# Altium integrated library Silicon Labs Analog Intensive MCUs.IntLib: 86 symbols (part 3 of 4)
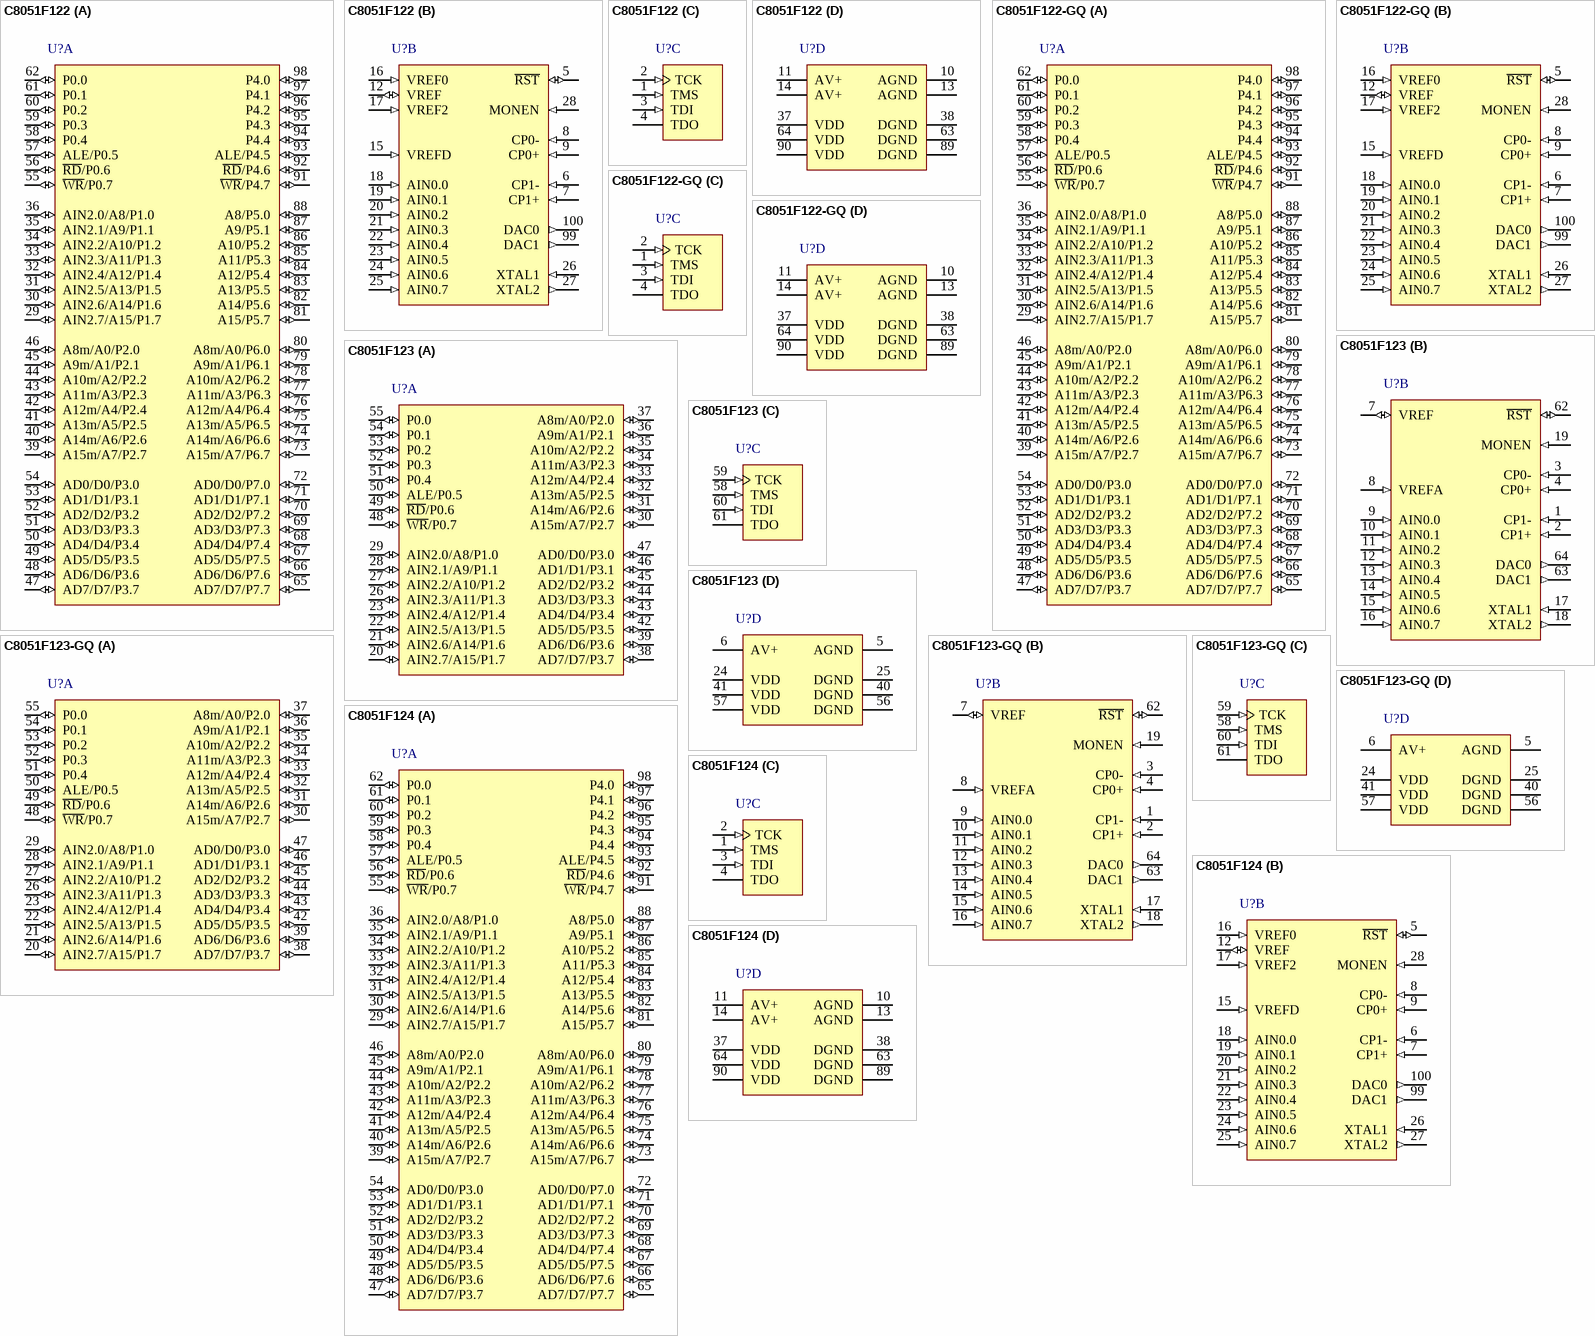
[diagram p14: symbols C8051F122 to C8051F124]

## C8051F123-GQ
designator U?
Mixed Signal 128KB ISP Flash MCU, 100 MIPS, 8448B RAM, 32 I/Os, 10-Bit & 8-Bit ADC, 12-Bit DAC, 64-Pin TQFP, Pb-Free; Manufacturer: Silicon Labs; PartNumber: C8051F123-GQ
footprint TQFP-64_N (Thin QFP, 64-Leads, Body 10x10mm, Pitch 0.5mm, IPC Medium Density)
footprint TQFP-64_L (Thin QFP, 64-Leads, Body 10x10mm, Pitch 0.5mm, IPC High Density)
footprint TQFP-64_M (Thin QFP, 64-Leads, Body 10x10mm, Pitch 0.5mm, IPC Low Density)
part A pins: 20 AIN2.7/A15/P1.7 (io), 21 AIN2.6/A14/P1.6 (io), 22 AIN2.5/A13/P1.5 (io), 23 AIN2.4/A12/P1.4 (io), 26 AIN2.3/A11/P1.3 (io), 27 AIN2.2/A10/P1.2 (io), 28 AIN2.1/A9/P1.1 (io), 29 AIN2.0/A8/P1.0 (io), 30 A15m/A7/P2.7 (io), 31 A14m/A6/P2.6 (io), 32 A13m/A5/P2.5 (io), 33 A12m/A4/P2.4 (io), 34 A11m/A3/P2.3 (io), 35 A10m/A2/P2.2 (io), 36 A9m/A1/P2.1 (io), 37 A8m/A0/P2.0 (io), 38 AD7/D7/P3.7 (io), 39 AD6/D6/P3.6 (io), 42 AD5/D5/P3.5 (io), 43 AD4/D4/P3.4 (io), 44 AD3/D3/P3.3 (io), 45 AD2/D2/P3.2 (io), 46 AD1/D1/P3.1 (io), 47 AD0/D0/P3.0 (io), 48 ~{WR}/P0.7 (io), 49 ~{RD}/P0.6 (io), 50 ALE/P0.5 (io), 51 P0.4 (io), 52 P0.3 (io), 53 P0.2 (io), 54 P0.1 (io), 55 P0.0 (io)
part B pins: 1 CP1- (in), 2 CP1+ (in), 3 CP0- (in), 4 CP0+ (in), 7 VREF (io), 8 VREFA (in), 9 AIN0.0 (in), 10 AIN0.1 (in), 11 AIN0.2 (in), 12 AIN0.3 (in), 13 AIN0.4 (in), 14 AIN0.5 (in), 15 AIN0.6 (in), 16 AIN0.7 (in), 17 XTAL1 (in), 18 XTAL2 (out), 19 MONEN (in), 62 ~{RST} (io), 63 DAC1 (out), 64 DAC0 (out)
part C pins: 58 TMS (in), 59 TCK (in), 60 TDI (in), 61 TDO (hiz)
part D pins: 5 AGND (power), 6 AV+ (power), 24 VDD (power), 25 DGND (power), 40 DGND (power), 41 VDD (power), 56 DGND (power), 57 VDD (power)

## C8051F124
designator U?
Mixed Signal 128KB ISP Flash MCU, 50 MIPS, 8448B RAM, 64 I/Os, 12-Bit & 8-Bit ADC, 12-Bit DAC, 100-Pin TQFP; Manufacturer: Silicon Labs; PartNumber: C8051F124
footprint TQFP-100_N (Thin QFP, 100-Leads, Body 14x14mm, Pitch 0.5mm, IPC Medium Density)
footprint TQFP-100_L (Thin QFP, 100-Leads, Body 14x14mm, Pitch 0.5mm, IPC High Density)
footprint TQFP-100_M (Thin QFP, 100-Leads, Body 14x14mm, Pitch 0.5mm, IPC Low Density)
part A pins: 29 AIN2.7/A15/P1.7 (io), 30 AIN2.6/A14/P1.6 (io), 31 AIN2.5/A13/P1.5 (io), 32 AIN2.4/A12/P1.4 (io), 33 AIN2.3/A11/P1.3 (io), 34 AIN2.2/A10/P1.2 (io), 35 AIN2.1/A9/P1.1 (io), 36 AIN2.0/A8/P1.0 (io), 39 A15m/A7/P2.7 (io), 40 A14m/A6/P2.6 (io), 41 A13m/A5/P2.5 (io), 42 A12m/A4/P2.4 (io), 43 A11m/A3/P2.3 (io), 44 A10m/A2/P2.2 (io), 45 A9m/A1/P2.1 (io), 46 A8m/A0/P2.0 (io), 47 AD7/D7/P3.7 (io), 48 AD6/D6/P3.6 (io), 49 AD5/D5/P3.5 (io), 50 AD4/D4/P3.4 (io), 51 AD3/D3/P3.3 (io), 52 AD2/D2/P3.2 (io), 53 AD1/D1/P3.1 (io), 54 AD0/D0/P3.0 (io), 55 ~{WR}/P0.7 (io), 56 ~{RD}/P0.6 (io), 57 ALE/P0.5 (io), 58 P0.4 (io), 59 P0.3 (io), 60 P0.2 (io), 61 P0.1 (io), 62 P0.0 (io), 65 AD7/D7/P7.7 (io), 66 AD6/D6/P7.6 (io), 67 AD5/D5/P7.5 (io), 68 AD4/D4/P7.4 (io), 69 AD3/D3/P7.3 (io), 70 AD2/D2/P7.2 (io), 71 AD1/D1/P7.1 (io), 72 AD0/D0/P7.0 (io), 73 A15m/A7/P6.7 (io), 74 A14m/A6/P6.6 (io), 75 A13m/A5/P6.5 (io), 76 A12m/A4/P6.4 (io), 77 A11m/A3/P6.3 (io), 78 A10m/A2/P6.2 (io), 79 A9m/A1/P6.1 (io), 80 A8m/A0/P6.0 (io), 81 A15/P5.7 (io), 82 A14/P5.6 (io), 83 A13/P5.5 (io), 84 A12/P5.4 (io), 85 A11/P5.3 (io), 86 A10/P5.2 (io), 87 A9/P5.1 (io), 88 A8/P5.0 (io), 91 ~{WR}/P4.7 (io), 92 ~{RD}/P4.6 (io), 93 ALE/P4.5 (io), 94 P4.4 (io), 95 P4.3 (io), 96 P4.2 (io), 97 P4.1 (io), 98 P4.0 (io)
part B pins: 5 ~{RST} (io), 6 CP1- (in), 7 CP1+ (in), 8 CP0- (in), 9 CP0+ (in), 12 VREF (io), 15 VREFD (in), 16 VREF0 (in), 17 VREF2 (in), 18 AIN0.0 (in), 19 AIN0.1 (in), 20 AIN0.2 (in), 21 AIN0.3 (in), 22 AIN0.4 (in), 23 AIN0.5 (in), 24 AIN0.6 (in), 25 AIN0.7 (in), 26 XTAL1 (in), 27 XTAL2 (out), 28 MONEN (in), 99 DAC1 (out), 100 DAC0 (out)
part C pins: 1 TMS (in), 2 TCK (in), 3 TDI (in), 4 TDO (hiz)
part D pins: 10 AGND (power), 11 AV+ (power), 13 AGND (power), 14 AV+ (power), 37 VDD (power), 38 DGND (power), 63 DGND (power), 64 VDD (power), 89 DGND (power), 90 VDD (power)

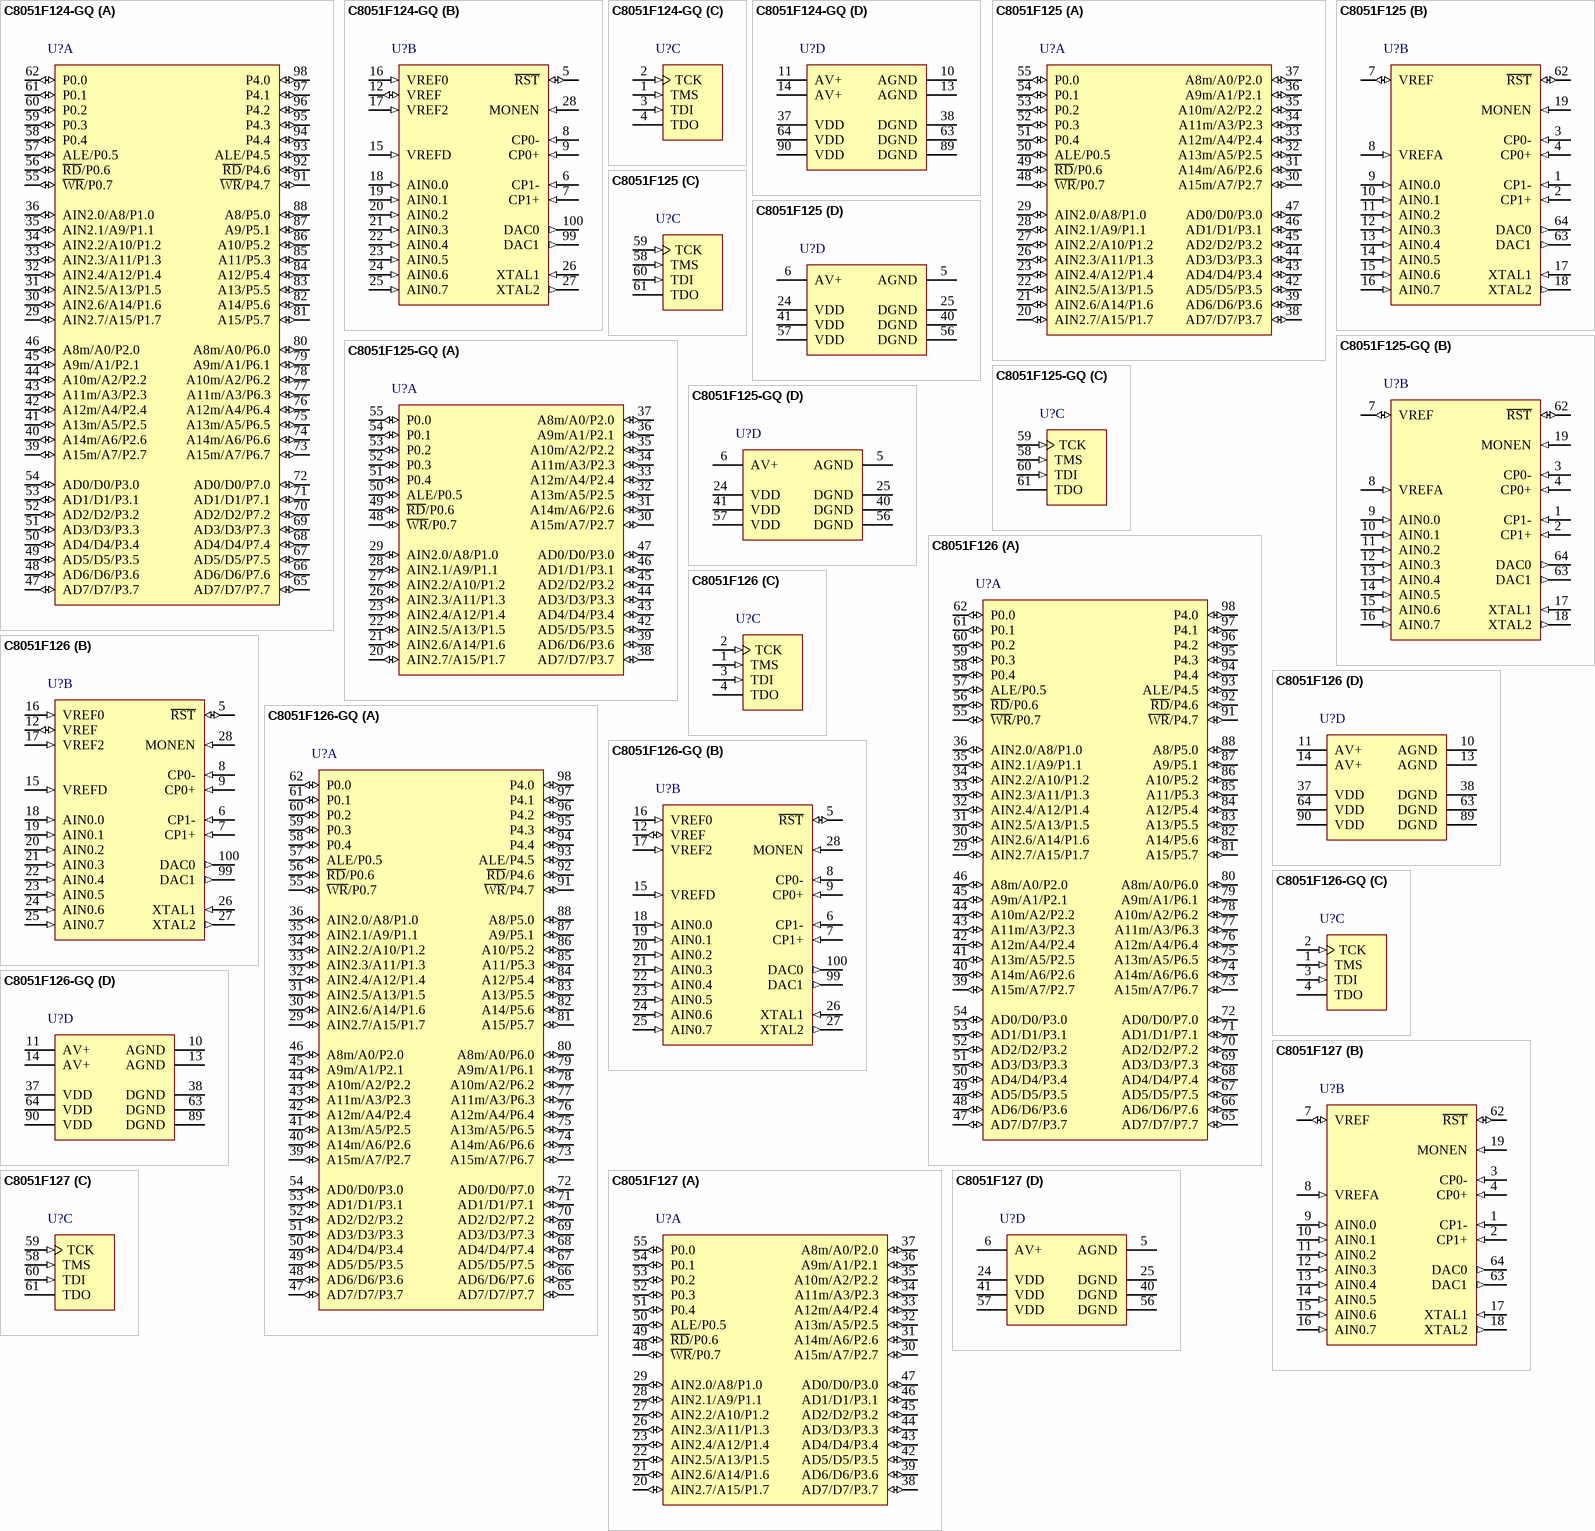
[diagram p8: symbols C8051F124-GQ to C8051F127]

## C8051F124-GQ
designator U?
Mixed Signal 128KB ISP Flash MCU, 50 MIPS, 8448B RAM, 64 I/Os, 12-Bit & 8-Bit ADC, 12-Bit DAC, 100-Pin TQFP, Pb-Free; Manufacturer: Silicon Labs; PartNumber: C8051F124-GQ
footprint TQFP-100_N (Thin QFP, 100-Leads, Body 14x14mm, Pitch 0.5mm, IPC Medium Density)
footprint TQFP-100_L (Thin QFP, 100-Leads, Body 14x14mm, Pitch 0.5mm, IPC High Density)
footprint TQFP-100_M (Thin QFP, 100-Leads, Body 14x14mm, Pitch 0.5mm, IPC Low Density)
part A pins: 29 AIN2.7/A15/P1.7 (io), 30 AIN2.6/A14/P1.6 (io), 31 AIN2.5/A13/P1.5 (io), 32 AIN2.4/A12/P1.4 (io), 33 AIN2.3/A11/P1.3 (io), 34 AIN2.2/A10/P1.2 (io), 35 AIN2.1/A9/P1.1 (io), 36 AIN2.0/A8/P1.0 (io), 39 A15m/A7/P2.7 (io), 40 A14m/A6/P2.6 (io), 41 A13m/A5/P2.5 (io), 42 A12m/A4/P2.4 (io), 43 A11m/A3/P2.3 (io), 44 A10m/A2/P2.2 (io), 45 A9m/A1/P2.1 (io), 46 A8m/A0/P2.0 (io), 47 AD7/D7/P3.7 (io), 48 AD6/D6/P3.6 (io), 49 AD5/D5/P3.5 (io), 50 AD4/D4/P3.4 (io), 51 AD3/D3/P3.3 (io), 52 AD2/D2/P3.2 (io), 53 AD1/D1/P3.1 (io), 54 AD0/D0/P3.0 (io), 55 ~{WR}/P0.7 (io), 56 ~{RD}/P0.6 (io), 57 ALE/P0.5 (io), 58 P0.4 (io), 59 P0.3 (io), 60 P0.2 (io), 61 P0.1 (io), 62 P0.0 (io), 65 AD7/D7/P7.7 (io), 66 AD6/D6/P7.6 (io), 67 AD5/D5/P7.5 (io), 68 AD4/D4/P7.4 (io), 69 AD3/D3/P7.3 (io), 70 AD2/D2/P7.2 (io), 71 AD1/D1/P7.1 (io), 72 AD0/D0/P7.0 (io), 73 A15m/A7/P6.7 (io), 74 A14m/A6/P6.6 (io), 75 A13m/A5/P6.5 (io), 76 A12m/A4/P6.4 (io), 77 A11m/A3/P6.3 (io), 78 A10m/A2/P6.2 (io), 79 A9m/A1/P6.1 (io), 80 A8m/A0/P6.0 (io), 81 A15/P5.7 (io), 82 A14/P5.6 (io), 83 A13/P5.5 (io), 84 A12/P5.4 (io), 85 A11/P5.3 (io), 86 A10/P5.2 (io), 87 A9/P5.1 (io), 88 A8/P5.0 (io), 91 ~{WR}/P4.7 (io), 92 ~{RD}/P4.6 (io), 93 ALE/P4.5 (io), 94 P4.4 (io), 95 P4.3 (io), 96 P4.2 (io), 97 P4.1 (io), 98 P4.0 (io)
part B pins: 5 ~{RST} (io), 6 CP1- (in), 7 CP1+ (in), 8 CP0- (in), 9 CP0+ (in), 12 VREF (io), 15 VREFD (in), 16 VREF0 (in), 17 VREF2 (in), 18 AIN0.0 (in), 19 AIN0.1 (in), 20 AIN0.2 (in), 21 AIN0.3 (in), 22 AIN0.4 (in), 23 AIN0.5 (in), 24 AIN0.6 (in), 25 AIN0.7 (in), 26 XTAL1 (in), 27 XTAL2 (out), 28 MONEN (in), 99 DAC1 (out), 100 DAC0 (out)
part C pins: 1 TMS (in), 2 TCK (in), 3 TDI (in), 4 TDO (hiz)
part D pins: 10 AGND (power), 11 AV+ (power), 13 AGND (power), 14 AV+ (power), 37 VDD (power), 38 DGND (power), 63 DGND (power), 64 VDD (power), 89 DGND (power), 90 VDD (power)

## C8051F125
designator U?
Mixed Signal 128KB ISP Flash MCU, 50 MIPS, 8448B RAM, 32 I/Os, 12-Bit & 8-Bit ADC, 12-Bit DAC, 64-Pin TQFP; Manufacturer: Silicon Labs; PartNumber: C8051F125
footprint TQFP-64_N (Thin QFP, 64-Leads, Body 10x10mm, Pitch 0.5mm, IPC Medium Density)
footprint TQFP-64_L (Thin QFP, 64-Leads, Body 10x10mm, Pitch 0.5mm, IPC High Density)
footprint TQFP-64_M (Thin QFP, 64-Leads, Body 10x10mm, Pitch 0.5mm, IPC Low Density)
part A pins: 20 AIN2.7/A15/P1.7 (io), 21 AIN2.6/A14/P1.6 (io), 22 AIN2.5/A13/P1.5 (io), 23 AIN2.4/A12/P1.4 (io), 26 AIN2.3/A11/P1.3 (io), 27 AIN2.2/A10/P1.2 (io), 28 AIN2.1/A9/P1.1 (io), 29 AIN2.0/A8/P1.0 (io), 30 A15m/A7/P2.7 (io), 31 A14m/A6/P2.6 (io), 32 A13m/A5/P2.5 (io), 33 A12m/A4/P2.4 (io), 34 A11m/A3/P2.3 (io), 35 A10m/A2/P2.2 (io), 36 A9m/A1/P2.1 (io), 37 A8m/A0/P2.0 (io), 38 AD7/D7/P3.7 (io), 39 AD6/D6/P3.6 (io), 42 AD5/D5/P3.5 (io), 43 AD4/D4/P3.4 (io), 44 AD3/D3/P3.3 (io), 45 AD2/D2/P3.2 (io), 46 AD1/D1/P3.1 (io), 47 AD0/D0/P3.0 (io), 48 ~{WR}/P0.7 (io), 49 ~{RD}/P0.6 (io), 50 ALE/P0.5 (io), 51 P0.4 (io), 52 P0.3 (io), 53 P0.2 (io), 54 P0.1 (io), 55 P0.0 (io)
part B pins: 1 CP1- (in), 2 CP1+ (in), 3 CP0- (in), 4 CP0+ (in), 7 VREF (io), 8 VREFA (in), 9 AIN0.0 (in), 10 AIN0.1 (in), 11 AIN0.2 (in), 12 AIN0.3 (in), 13 AIN0.4 (in), 14 AIN0.5 (in), 15 AIN0.6 (in), 16 AIN0.7 (in), 17 XTAL1 (in), 18 XTAL2 (out), 19 MONEN (in), 62 ~{RST} (io), 63 DAC1 (out), 64 DAC0 (out)
part C pins: 58 TMS (in), 59 TCK (in), 60 TDI (in), 61 TDO (hiz)
part D pins: 5 AGND (power), 6 AV+ (power), 24 VDD (power), 25 DGND (power), 40 DGND (power), 41 VDD (power), 56 DGND (power), 57 VDD (power)

## C8051F125-GQ
designator U?
Mixed Signal 128KB ISP Flash MCU, 50 MIPS, 8448B RAM, 32 I/Os, 12-Bit & 8-Bit ADC, 12-Bit DAC, 64-Pin TQFP, Pb-Free; Manufacturer: Silicon Labs; PartNumber: C8051F125-GQ
footprint TQFP-64_N (Thin QFP, 64-Leads, Body 10x10mm, Pitch 0.5mm, IPC Medium Density)
footprint TQFP-64_L (Thin QFP, 64-Leads, Body 10x10mm, Pitch 0.5mm, IPC High Density)
footprint TQFP-64_M (Thin QFP, 64-Leads, Body 10x10mm, Pitch 0.5mm, IPC Low Density)
part A pins: 20 AIN2.7/A15/P1.7 (io), 21 AIN2.6/A14/P1.6 (io), 22 AIN2.5/A13/P1.5 (io), 23 AIN2.4/A12/P1.4 (io), 26 AIN2.3/A11/P1.3 (io), 27 AIN2.2/A10/P1.2 (io), 28 AIN2.1/A9/P1.1 (io), 29 AIN2.0/A8/P1.0 (io), 30 A15m/A7/P2.7 (io), 31 A14m/A6/P2.6 (io), 32 A13m/A5/P2.5 (io), 33 A12m/A4/P2.4 (io), 34 A11m/A3/P2.3 (io), 35 A10m/A2/P2.2 (io), 36 A9m/A1/P2.1 (io), 37 A8m/A0/P2.0 (io), 38 AD7/D7/P3.7 (io), 39 AD6/D6/P3.6 (io), 42 AD5/D5/P3.5 (io), 43 AD4/D4/P3.4 (io), 44 AD3/D3/P3.3 (io), 45 AD2/D2/P3.2 (io), 46 AD1/D1/P3.1 (io), 47 AD0/D0/P3.0 (io), 48 ~{WR}/P0.7 (io), 49 ~{RD}/P0.6 (io), 50 ALE/P0.5 (io), 51 P0.4 (io), 52 P0.3 (io), 53 P0.2 (io), 54 P0.1 (io), 55 P0.0 (io)
part B pins: 1 CP1- (in), 2 CP1+ (in), 3 CP0- (in), 4 CP0+ (in), 7 VREF (io), 8 VREFA (in), 9 AIN0.0 (in), 10 AIN0.1 (in), 11 AIN0.2 (in), 12 AIN0.3 (in), 13 AIN0.4 (in), 14 AIN0.5 (in), 15 AIN0.6 (in), 16 AIN0.7 (in), 17 XTAL1 (in), 18 XTAL2 (out), 19 MONEN (in), 62 ~{RST} (io), 63 DAC1 (out), 64 DAC0 (out)
part C pins: 58 TMS (in), 59 TCK (in), 60 TDI (in), 61 TDO (hiz)
part D pins: 5 AGND (power), 6 AV+ (power), 24 VDD (power), 25 DGND (power), 40 DGND (power), 41 VDD (power), 56 DGND (power), 57 VDD (power)

## C8051F126
designator U?
Mixed Signal 128KB ISP Flash MCU, 50 MIPS, 8448B RAM, 64 I/Os, 10-Bit & 8-Bit ADC, 12-Bit DAC, 100-Pin TQFP; Manufacturer: Silicon Labs; PartNumber: C8051F126
footprint TQFP-100_N (Thin QFP, 100-Leads, Body 14x14mm, Pitch 0.5mm, IPC Medium Density)
footprint TQFP-100_L (Thin QFP, 100-Leads, Body 14x14mm, Pitch 0.5mm, IPC High Density)
footprint TQFP-100_M (Thin QFP, 100-Leads, Body 14x14mm, Pitch 0.5mm, IPC Low Density)
part A pins: 29 AIN2.7/A15/P1.7 (io), 30 AIN2.6/A14/P1.6 (io), 31 AIN2.5/A13/P1.5 (io), 32 AIN2.4/A12/P1.4 (io), 33 AIN2.3/A11/P1.3 (io), 34 AIN2.2/A10/P1.2 (io), 35 AIN2.1/A9/P1.1 (io), 36 AIN2.0/A8/P1.0 (io), 39 A15m/A7/P2.7 (io), 40 A14m/A6/P2.6 (io), 41 A13m/A5/P2.5 (io), 42 A12m/A4/P2.4 (io), 43 A11m/A3/P2.3 (io), 44 A10m/A2/P2.2 (io), 45 A9m/A1/P2.1 (io), 46 A8m/A0/P2.0 (io), 47 AD7/D7/P3.7 (io), 48 AD6/D6/P3.6 (io), 49 AD5/D5/P3.5 (io), 50 AD4/D4/P3.4 (io), 51 AD3/D3/P3.3 (io), 52 AD2/D2/P3.2 (io), 53 AD1/D1/P3.1 (io), 54 AD0/D0/P3.0 (io), 55 ~{WR}/P0.7 (io), 56 ~{RD}/P0.6 (io), 57 ALE/P0.5 (io), 58 P0.4 (io), 59 P0.3 (io), 60 P0.2 (io), 61 P0.1 (io), 62 P0.0 (io), 65 AD7/D7/P7.7 (io), 66 AD6/D6/P7.6 (io), 67 AD5/D5/P7.5 (io), 68 AD4/D4/P7.4 (io), 69 AD3/D3/P7.3 (io), 70 AD2/D2/P7.2 (io), 71 AD1/D1/P7.1 (io), 72 AD0/D0/P7.0 (io), 73 A15m/A7/P6.7 (io), 74 A14m/A6/P6.6 (io), 75 A13m/A5/P6.5 (io), 76 A12m/A4/P6.4 (io), 77 A11m/A3/P6.3 (io), 78 A10m/A2/P6.2 (io), 79 A9m/A1/P6.1 (io), 80 A8m/A0/P6.0 (io), 81 A15/P5.7 (io), 82 A14/P5.6 (io), 83 A13/P5.5 (io), 84 A12/P5.4 (io), 85 A11/P5.3 (io), 86 A10/P5.2 (io), 87 A9/P5.1 (io), 88 A8/P5.0 (io), 91 ~{WR}/P4.7 (io), 92 ~{RD}/P4.6 (io), 93 ALE/P4.5 (io), 94 P4.4 (io), 95 P4.3 (io), 96 P4.2 (io), 97 P4.1 (io), 98 P4.0 (io)
part B pins: 5 ~{RST} (io), 6 CP1- (in), 7 CP1+ (in), 8 CP0- (in), 9 CP0+ (in), 12 VREF (io), 15 VREFD (in), 16 VREF0 (in), 17 VREF2 (in), 18 AIN0.0 (in), 19 AIN0.1 (in), 20 AIN0.2 (in), 21 AIN0.3 (in), 22 AIN0.4 (in), 23 AIN0.5 (in), 24 AIN0.6 (in), 25 AIN0.7 (in), 26 XTAL1 (in), 27 XTAL2 (out), 28 MONEN (in), 99 DAC1 (out), 100 DAC0 (out)
part C pins: 1 TMS (in), 2 TCK (in), 3 TDI (in), 4 TDO (hiz)
part D pins: 10 AGND (power), 11 AV+ (power), 13 AGND (power), 14 AV+ (power), 37 VDD (power), 38 DGND (power), 63 DGND (power), 64 VDD (power), 89 DGND (power), 90 VDD (power)

## C8051F126-GQ
designator U?
Mixed Signal 128KB ISP Flash MCU, 50 MIPS, 8448B RAM, 64 I/Os, 10-Bit & 8-Bit ADC, 12-Bit DAC, 100-Pin TQFP, Pb-Free; Manufacturer: Silicon Labs; PartNumber: C8051F126-GQ
footprint TQFP-100_N (Thin QFP, 100-Leads, Body 14x14mm, Pitch 0.5mm, IPC Medium Density)
footprint TQFP-100_L (Thin QFP, 100-Leads, Body 14x14mm, Pitch 0.5mm, IPC High Density)
footprint TQFP-100_M (Thin QFP, 100-Leads, Body 14x14mm, Pitch 0.5mm, IPC Low Density)
part A pins: 29 AIN2.7/A15/P1.7 (io), 30 AIN2.6/A14/P1.6 (io), 31 AIN2.5/A13/P1.5 (io), 32 AIN2.4/A12/P1.4 (io), 33 AIN2.3/A11/P1.3 (io), 34 AIN2.2/A10/P1.2 (io), 35 AIN2.1/A9/P1.1 (io), 36 AIN2.0/A8/P1.0 (io), 39 A15m/A7/P2.7 (io), 40 A14m/A6/P2.6 (io), 41 A13m/A5/P2.5 (io), 42 A12m/A4/P2.4 (io), 43 A11m/A3/P2.3 (io), 44 A10m/A2/P2.2 (io), 45 A9m/A1/P2.1 (io), 46 A8m/A0/P2.0 (io), 47 AD7/D7/P3.7 (io), 48 AD6/D6/P3.6 (io), 49 AD5/D5/P3.5 (io), 50 AD4/D4/P3.4 (io), 51 AD3/D3/P3.3 (io), 52 AD2/D2/P3.2 (io), 53 AD1/D1/P3.1 (io), 54 AD0/D0/P3.0 (io), 55 ~{WR}/P0.7 (io), 56 ~{RD}/P0.6 (io), 57 ALE/P0.5 (io), 58 P0.4 (io), 59 P0.3 (io), 60 P0.2 (io), 61 P0.1 (io), 62 P0.0 (io), 65 AD7/D7/P7.7 (io), 66 AD6/D6/P7.6 (io), 67 AD5/D5/P7.5 (io), 68 AD4/D4/P7.4 (io), 69 AD3/D3/P7.3 (io), 70 AD2/D2/P7.2 (io), 71 AD1/D1/P7.1 (io), 72 AD0/D0/P7.0 (io), 73 A15m/A7/P6.7 (io), 74 A14m/A6/P6.6 (io), 75 A13m/A5/P6.5 (io), 76 A12m/A4/P6.4 (io), 77 A11m/A3/P6.3 (io), 78 A10m/A2/P6.2 (io), 79 A9m/A1/P6.1 (io), 80 A8m/A0/P6.0 (io), 81 A15/P5.7 (io), 82 A14/P5.6 (io), 83 A13/P5.5 (io), 84 A12/P5.4 (io), 85 A11/P5.3 (io), 86 A10/P5.2 (io), 87 A9/P5.1 (io), 88 A8/P5.0 (io), 91 ~{WR}/P4.7 (io), 92 ~{RD}/P4.6 (io), 93 ALE/P4.5 (io), 94 P4.4 (io), 95 P4.3 (io), 96 P4.2 (io), 97 P4.1 (io), 98 P4.0 (io)
part B pins: 5 ~{RST} (io), 6 CP1- (in), 7 CP1+ (in), 8 CP0- (in), 9 CP0+ (in), 12 VREF (io), 15 VREFD (in), 16 VREF0 (in), 17 VREF2 (in), 18 AIN0.0 (in), 19 AIN0.1 (in), 20 AIN0.2 (in), 21 AIN0.3 (in), 22 AIN0.4 (in), 23 AIN0.5 (in), 24 AIN0.6 (in), 25 AIN0.7 (in), 26 XTAL1 (in), 27 XTAL2 (out), 28 MONEN (in), 99 DAC1 (out), 100 DAC0 (out)
part C pins: 1 TMS (in), 2 TCK (in), 3 TDI (in), 4 TDO (hiz)
part D pins: 10 AGND (power), 11 AV+ (power), 13 AGND (power), 14 AV+ (power), 37 VDD (power), 38 DGND (power), 63 DGND (power), 64 VDD (power), 89 DGND (power), 90 VDD (power)

## C8051F127
designator U?
Mixed Signal 128KB ISP Flash MCU, 50 MIPS, 8448B RAM, 32 I/Os, 10-Bit & 8-Bit ADC, 12-Bit DAC, 64-Pin TQFP; Manufacturer: Silicon Labs; PartNumber: C8051F127
footprint TQFP-64_N (Thin QFP, 64-Leads, Body 10x10mm, Pitch 0.5mm, IPC Medium Density)
footprint TQFP-64_L (Thin QFP, 64-Leads, Body 10x10mm, Pitch 0.5mm, IPC High Density)
footprint TQFP-64_M (Thin QFP, 64-Leads, Body 10x10mm, Pitch 0.5mm, IPC Low Density)
part A pins: 20 AIN2.7/A15/P1.7 (io), 21 AIN2.6/A14/P1.6 (io), 22 AIN2.5/A13/P1.5 (io), 23 AIN2.4/A12/P1.4 (io), 26 AIN2.3/A11/P1.3 (io), 27 AIN2.2/A10/P1.2 (io), 28 AIN2.1/A9/P1.1 (io), 29 AIN2.0/A8/P1.0 (io), 30 A15m/A7/P2.7 (io), 31 A14m/A6/P2.6 (io), 32 A13m/A5/P2.5 (io), 33 A12m/A4/P2.4 (io), 34 A11m/A3/P2.3 (io), 35 A10m/A2/P2.2 (io), 36 A9m/A1/P2.1 (io), 37 A8m/A0/P2.0 (io), 38 AD7/D7/P3.7 (io), 39 AD6/D6/P3.6 (io), 42 AD5/D5/P3.5 (io), 43 AD4/D4/P3.4 (io), 44 AD3/D3/P3.3 (io), 45 AD2/D2/P3.2 (io), 46 AD1/D1/P3.1 (io), 47 AD0/D0/P3.0 (io), 48 ~{WR}/P0.7 (io), 49 ~{RD}/P0.6 (io), 50 ALE/P0.5 (io), 51 P0.4 (io), 52 P0.3 (io), 53 P0.2 (io), 54 P0.1 (io), 55 P0.0 (io)
part B pins: 1 CP1- (in), 2 CP1+ (in), 3 CP0- (in), 4 CP0+ (in), 7 VREF (io), 8 VREFA (in), 9 AIN0.0 (in), 10 AIN0.1 (in), 11 AIN0.2 (in), 12 AIN0.3 (in), 13 AIN0.4 (in), 14 AIN0.5 (in), 15 AIN0.6 (in), 16 AIN0.7 (in), 17 XTAL1 (in), 18 XTAL2 (out), 19 MONEN (in), 62 ~{RST} (io), 63 DAC1 (out), 64 DAC0 (out)
part C pins: 58 TMS (in), 59 TCK (in), 60 TDI (in), 61 TDO (hiz)
part D pins: 5 AGND (power), 6 AV+ (power), 24 VDD (power), 25 DGND (power), 40 DGND (power), 41 VDD (power), 56 DGND (power), 57 VDD (power)

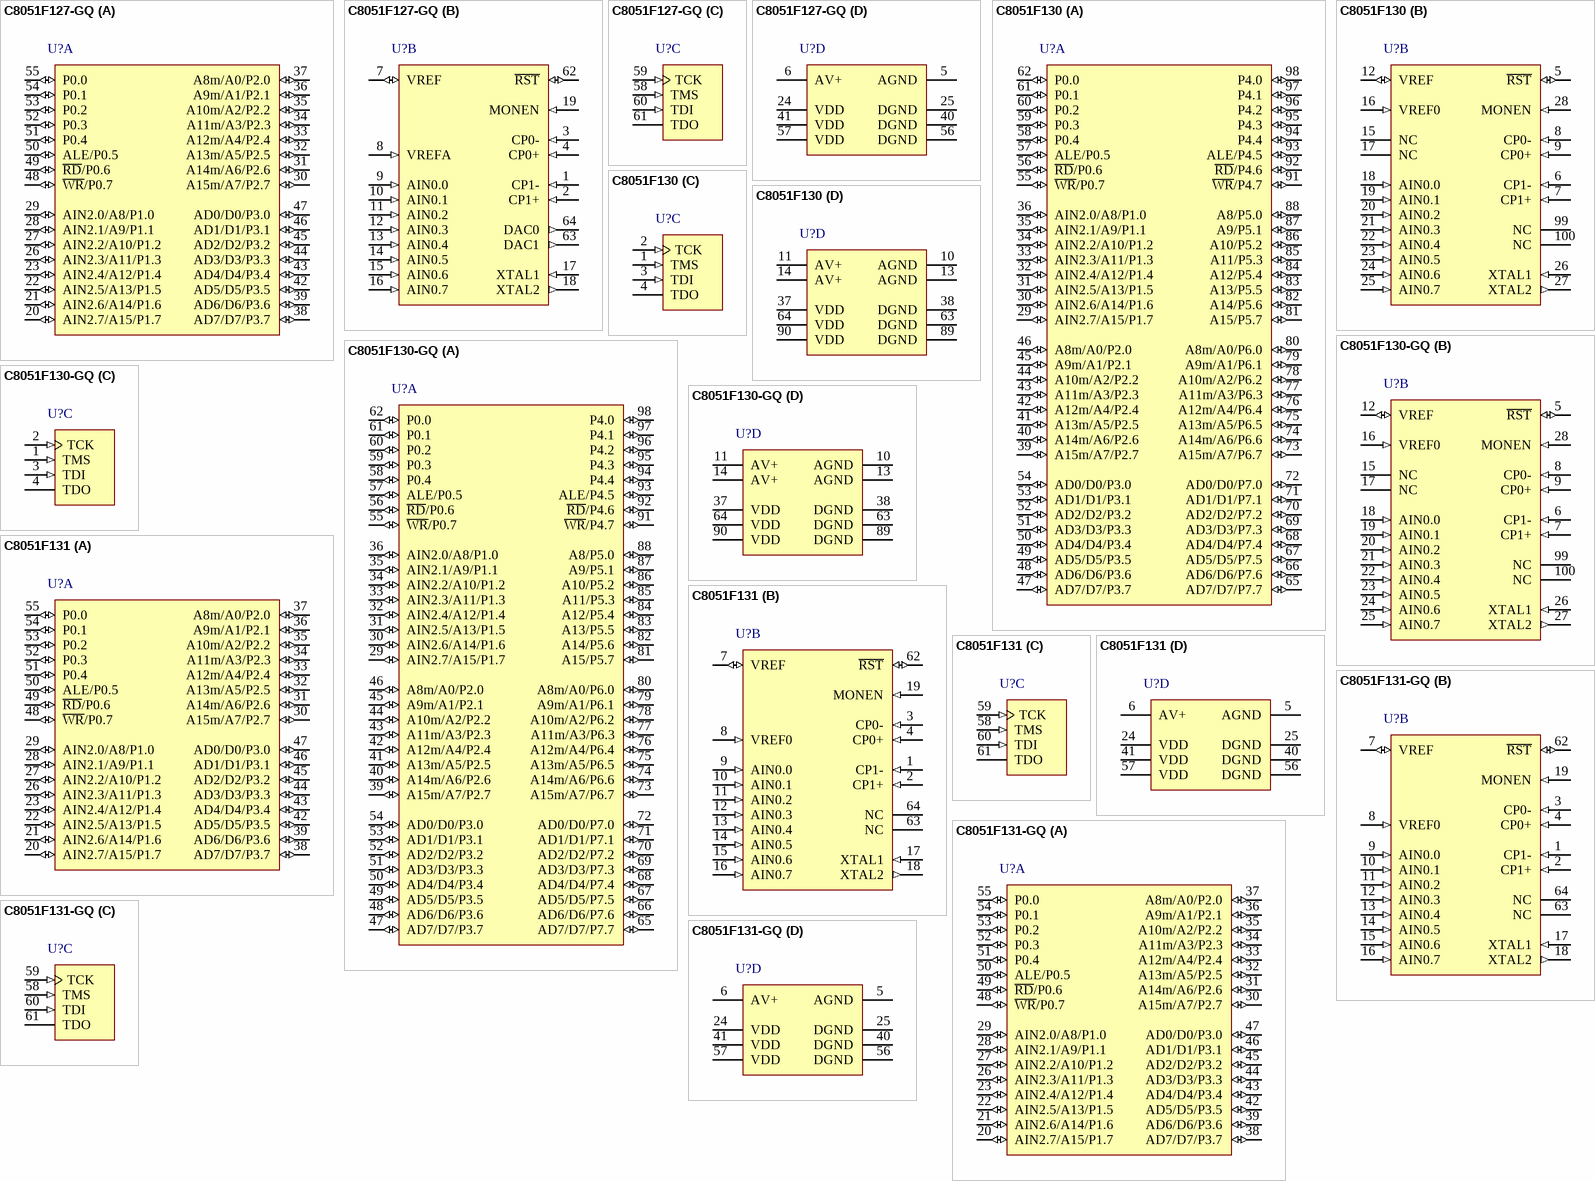
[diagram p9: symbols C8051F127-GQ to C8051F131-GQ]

## C8051F127-GQ
designator U?
Mixed Signal 128KB ISP Flash MCU, 50 MIPS, 8448B RAM, 32 I/Os, 10-Bit & 8-Bit ADC, 12-Bit DAC, 64-Pin TQFP, Pb-Free; Manufacturer: Silicon Labs; PartNumber: C8051F127-GQ
footprint TQFP-64_N (Thin QFP, 64-Leads, Body 10x10mm, Pitch 0.5mm, IPC Medium Density)
footprint TQFP-64_L (Thin QFP, 64-Leads, Body 10x10mm, Pitch 0.5mm, IPC High Density)
footprint TQFP-64_M (Thin QFP, 64-Leads, Body 10x10mm, Pitch 0.5mm, IPC Low Density)
part A pins: 20 AIN2.7/A15/P1.7 (io), 21 AIN2.6/A14/P1.6 (io), 22 AIN2.5/A13/P1.5 (io), 23 AIN2.4/A12/P1.4 (io), 26 AIN2.3/A11/P1.3 (io), 27 AIN2.2/A10/P1.2 (io), 28 AIN2.1/A9/P1.1 (io), 29 AIN2.0/A8/P1.0 (io), 30 A15m/A7/P2.7 (io), 31 A14m/A6/P2.6 (io), 32 A13m/A5/P2.5 (io), 33 A12m/A4/P2.4 (io), 34 A11m/A3/P2.3 (io), 35 A10m/A2/P2.2 (io), 36 A9m/A1/P2.1 (io), 37 A8m/A0/P2.0 (io), 38 AD7/D7/P3.7 (io), 39 AD6/D6/P3.6 (io), 42 AD5/D5/P3.5 (io), 43 AD4/D4/P3.4 (io), 44 AD3/D3/P3.3 (io), 45 AD2/D2/P3.2 (io), 46 AD1/D1/P3.1 (io), 47 AD0/D0/P3.0 (io), 48 ~{WR}/P0.7 (io), 49 ~{RD}/P0.6 (io), 50 ALE/P0.5 (io), 51 P0.4 (io), 52 P0.3 (io), 53 P0.2 (io), 54 P0.1 (io), 55 P0.0 (io)
part B pins: 1 CP1- (in), 2 CP1+ (in), 3 CP0- (in), 4 CP0+ (in), 7 VREF (io), 8 VREFA (in), 9 AIN0.0 (in), 10 AIN0.1 (in), 11 AIN0.2 (in), 12 AIN0.3 (in), 13 AIN0.4 (in), 14 AIN0.5 (in), 15 AIN0.6 (in), 16 AIN0.7 (in), 17 XTAL1 (in), 18 XTAL2 (out), 19 MONEN (in), 62 ~{RST} (io), 63 DAC1 (out), 64 DAC0 (out)
part C pins: 58 TMS (in), 59 TCK (in), 60 TDI (in), 61 TDO (hiz)
part D pins: 5 AGND (power), 6 AV+ (power), 24 VDD (power), 25 DGND (power), 40 DGND (power), 41 VDD (power), 56 DGND (power), 57 VDD (power)

## C8051F130
designator U?
Mixed Signal 128KB ISP Flash MCU, 100 MIPS, 8448B RAM, 64 I/Os, 10-Bit ADC, 100-Pin TQFP; Manufacturer: Silicon Labs; PartNumber: C8051F130
footprint TQFP-100_N (Thin QFP, 100-Leads, Body 14x14mm, Pitch 0.5mm, IPC Medium Density)
footprint TQFP-100_L (Thin QFP, 100-Leads, Body 14x14mm, Pitch 0.5mm, IPC High Density)
footprint TQFP-100_M (Thin QFP, 100-Leads, Body 14x14mm, Pitch 0.5mm, IPC Low Density)
part A pins: 29 AIN2.7/A15/P1.7 (io), 30 AIN2.6/A14/P1.6 (io), 31 AIN2.5/A13/P1.5 (io), 32 AIN2.4/A12/P1.4 (io), 33 AIN2.3/A11/P1.3 (io), 34 AIN2.2/A10/P1.2 (io), 35 AIN2.1/A9/P1.1 (io), 36 AIN2.0/A8/P1.0 (io), 39 A15m/A7/P2.7 (io), 40 A14m/A6/P2.6 (io), 41 A13m/A5/P2.5 (io), 42 A12m/A4/P2.4 (io), 43 A11m/A3/P2.3 (io), 44 A10m/A2/P2.2 (io), 45 A9m/A1/P2.1 (io), 46 A8m/A0/P2.0 (io), 47 AD7/D7/P3.7 (io), 48 AD6/D6/P3.6 (io), 49 AD5/D5/P3.5 (io), 50 AD4/D4/P3.4 (io), 51 AD3/D3/P3.3 (io), 52 AD2/D2/P3.2 (io), 53 AD1/D1/P3.1 (io), 54 AD0/D0/P3.0 (io), 55 ~{WR}/P0.7 (io), 56 ~{RD}/P0.6 (io), 57 ALE/P0.5 (io), 58 P0.4 (io), 59 P0.3 (io), 60 P0.2 (io), 61 P0.1 (io), 62 P0.0 (io), 65 AD7/D7/P7.7 (io), 66 AD6/D6/P7.6 (io), 67 AD5/D5/P7.5 (io), 68 AD4/D4/P7.4 (io), 69 AD3/D3/P7.3 (io), 70 AD2/D2/P7.2 (io), 71 AD1/D1/P7.1 (io), 72 AD0/D0/P7.0 (io), 73 A15m/A7/P6.7 (io), 74 A14m/A6/P6.6 (io), 75 A13m/A5/P6.5 (io), 76 A12m/A4/P6.4 (io), 77 A11m/A3/P6.3 (io), 78 A10m/A2/P6.2 (io), 79 A9m/A1/P6.1 (io), 80 A8m/A0/P6.0 (io), 81 A15/P5.7 (io), 82 A14/P5.6 (io), 83 A13/P5.5 (io), 84 A12/P5.4 (io), 85 A11/P5.3 (io), 86 A10/P5.2 (io), 87 A9/P5.1 (io), 88 A8/P5.0 (io), 91 ~{WR}/P4.7 (io), 92 ~{RD}/P4.6 (io), 93 ALE/P4.5 (io), 94 P4.4 (io), 95 P4.3 (io), 96 P4.2 (io), 97 P4.1 (io), 98 P4.0 (io)
part B pins: 5 ~{RST} (io), 6 CP1- (in), 7 CP1+ (in), 8 CP0- (in), 9 CP0+ (in), 12 VREF (io), 15 NC, 16 VREF0 (in), 17 NC, 18 AIN0.0 (in), 19 AIN0.1 (in), 20 AIN0.2 (in), 21 AIN0.3 (in), 22 AIN0.4 (in), 23 AIN0.5 (in), 24 AIN0.6 (in), 25 AIN0.7 (in), 26 XTAL1 (in), 27 XTAL2 (out), 28 MONEN (in), 99 NC, 100 NC
part C pins: 1 TMS (in), 2 TCK (in), 3 TDI (in), 4 TDO (hiz)
part D pins: 10 AGND (power), 11 AV+ (power), 13 AGND (power), 14 AV+ (power), 37 VDD (power), 38 DGND (power), 63 DGND (power), 64 VDD (power), 89 DGND (power), 90 VDD (power)

## C8051F130-GQ
designator U?
Mixed Signal 128KB ISP Flash MCU, 100 MIPS, 8448B RAM, 64 I/Os, 10-Bit ADC, 100-Pin TQFP, Pb-Free; Manufacturer: Silicon Labs; PartNumber: C8051F130-GQ
footprint TQFP-100_N (Thin QFP, 100-Leads, Body 14x14mm, Pitch 0.5mm, IPC Medium Density)
footprint TQFP-100_L (Thin QFP, 100-Leads, Body 14x14mm, Pitch 0.5mm, IPC High Density)
footprint TQFP-100_M (Thin QFP, 100-Leads, Body 14x14mm, Pitch 0.5mm, IPC Low Density)
part A pins: 29 AIN2.7/A15/P1.7 (io), 30 AIN2.6/A14/P1.6 (io), 31 AIN2.5/A13/P1.5 (io), 32 AIN2.4/A12/P1.4 (io), 33 AIN2.3/A11/P1.3 (io), 34 AIN2.2/A10/P1.2 (io), 35 AIN2.1/A9/P1.1 (io), 36 AIN2.0/A8/P1.0 (io), 39 A15m/A7/P2.7 (io), 40 A14m/A6/P2.6 (io), 41 A13m/A5/P2.5 (io), 42 A12m/A4/P2.4 (io), 43 A11m/A3/P2.3 (io), 44 A10m/A2/P2.2 (io), 45 A9m/A1/P2.1 (io), 46 A8m/A0/P2.0 (io), 47 AD7/D7/P3.7 (io), 48 AD6/D6/P3.6 (io), 49 AD5/D5/P3.5 (io), 50 AD4/D4/P3.4 (io), 51 AD3/D3/P3.3 (io), 52 AD2/D2/P3.2 (io), 53 AD1/D1/P3.1 (io), 54 AD0/D0/P3.0 (io), 55 ~{WR}/P0.7 (io), 56 ~{RD}/P0.6 (io), 57 ALE/P0.5 (io), 58 P0.4 (io), 59 P0.3 (io), 60 P0.2 (io), 61 P0.1 (io), 62 P0.0 (io), 65 AD7/D7/P7.7 (io), 66 AD6/D6/P7.6 (io), 67 AD5/D5/P7.5 (io), 68 AD4/D4/P7.4 (io), 69 AD3/D3/P7.3 (io), 70 AD2/D2/P7.2 (io), 71 AD1/D1/P7.1 (io), 72 AD0/D0/P7.0 (io), 73 A15m/A7/P6.7 (io), 74 A14m/A6/P6.6 (io), 75 A13m/A5/P6.5 (io), 76 A12m/A4/P6.4 (io), 77 A11m/A3/P6.3 (io), 78 A10m/A2/P6.2 (io), 79 A9m/A1/P6.1 (io), 80 A8m/A0/P6.0 (io), 81 A15/P5.7 (io), 82 A14/P5.6 (io), 83 A13/P5.5 (io), 84 A12/P5.4 (io), 85 A11/P5.3 (io), 86 A10/P5.2 (io), 87 A9/P5.1 (io), 88 A8/P5.0 (io), 91 ~{WR}/P4.7 (io), 92 ~{RD}/P4.6 (io), 93 ALE/P4.5 (io), 94 P4.4 (io), 95 P4.3 (io), 96 P4.2 (io), 97 P4.1 (io), 98 P4.0 (io)
part B pins: 5 ~{RST} (io), 6 CP1- (in), 7 CP1+ (in), 8 CP0- (in), 9 CP0+ (in), 12 VREF (io), 15 NC, 16 VREF0 (in), 17 NC, 18 AIN0.0 (in), 19 AIN0.1 (in), 20 AIN0.2 (in), 21 AIN0.3 (in), 22 AIN0.4 (in), 23 AIN0.5 (in), 24 AIN0.6 (in), 25 AIN0.7 (in), 26 XTAL1 (in), 27 XTAL2 (out), 28 MONEN (in), 99 NC, 100 NC
part C pins: 1 TMS (in), 2 TCK (in), 3 TDI (in), 4 TDO (hiz)
part D pins: 10 AGND (power), 11 AV+ (power), 13 AGND (power), 14 AV+ (power), 37 VDD (power), 38 DGND (power), 63 DGND (power), 64 VDD (power), 89 DGND (power), 90 VDD (power)

## C8051F131
designator U?
Mixed Signal 128KB ISP Flash MCU, 100 MIPS, 8448B RAM, 32 I/Os, 10-Bit ADC, 64-Pin TQFP; Manufacturer: Silicon Labs; PartNumber: C8051F131
footprint TQFP-64_N (Thin QFP, 64-Leads, Body 10x10mm, Pitch 0.5mm, IPC Medium Density)
footprint TQFP-64_L (Thin QFP, 64-Leads, Body 10x10mm, Pitch 0.5mm, IPC High Density)
footprint TQFP-64_M (Thin QFP, 64-Leads, Body 10x10mm, Pitch 0.5mm, IPC Low Density)
part A pins: 20 AIN2.7/A15/P1.7 (io), 21 AIN2.6/A14/P1.6 (io), 22 AIN2.5/A13/P1.5 (io), 23 AIN2.4/A12/P1.4 (io), 26 AIN2.3/A11/P1.3 (io), 27 AIN2.2/A10/P1.2 (io), 28 AIN2.1/A9/P1.1 (io), 29 AIN2.0/A8/P1.0 (io), 30 A15m/A7/P2.7 (io), 31 A14m/A6/P2.6 (io), 32 A13m/A5/P2.5 (io), 33 A12m/A4/P2.4 (io), 34 A11m/A3/P2.3 (io), 35 A10m/A2/P2.2 (io), 36 A9m/A1/P2.1 (io), 37 A8m/A0/P2.0 (io), 38 AD7/D7/P3.7 (io), 39 AD6/D6/P3.6 (io), 42 AD5/D5/P3.5 (io), 43 AD4/D4/P3.4 (io), 44 AD3/D3/P3.3 (io), 45 AD2/D2/P3.2 (io), 46 AD1/D1/P3.1 (io), 47 AD0/D0/P3.0 (io), 48 ~{WR}/P0.7 (io), 49 ~{RD}/P0.6 (io), 50 ALE/P0.5 (io), 51 P0.4 (io), 52 P0.3 (io), 53 P0.2 (io), 54 P0.1 (io), 55 P0.0 (io)
part B pins: 1 CP1- (in), 2 CP1+ (in), 3 CP0- (in), 4 CP0+ (in), 7 VREF (io), 8 VREF0 (in), 9 AIN0.0 (in), 10 AIN0.1 (in), 11 AIN0.2 (in), 12 AIN0.3 (in), 13 AIN0.4 (in), 14 AIN0.5 (in), 15 AIN0.6 (in), 16 AIN0.7 (in), 17 XTAL1 (in), 18 XTAL2 (out), 19 MONEN (in), 62 ~{RST} (io), 63 NC, 64 NC
part C pins: 58 TMS (in), 59 TCK (in), 60 TDI (in), 61 TDO (hiz)
part D pins: 5 AGND (power), 6 AV+ (power), 24 VDD (power), 25 DGND (power), 40 DGND (power), 41 VDD (power), 56 DGND (power), 57 VDD (power)

## C8051F131-GQ
designator U?
Mixed Signal 128KB ISP Flash MCU, 100 MIPS, 8448B RAM, 32 I/Os, 10-Bit ADC, 64-Pin TQFP, Pb-Free; Manufacturer: Silicon Labs; PartNumber: C8051F131-GQ
footprint TQFP-64_N (Thin QFP, 64-Leads, Body 10x10mm, Pitch 0.5mm, IPC Medium Density)
footprint TQFP-64_L (Thin QFP, 64-Leads, Body 10x10mm, Pitch 0.5mm, IPC High Density)
footprint TQFP-64_M (Thin QFP, 64-Leads, Body 10x10mm, Pitch 0.5mm, IPC Low Density)
part A pins: 20 AIN2.7/A15/P1.7 (io), 21 AIN2.6/A14/P1.6 (io), 22 AIN2.5/A13/P1.5 (io), 23 AIN2.4/A12/P1.4 (io), 26 AIN2.3/A11/P1.3 (io), 27 AIN2.2/A10/P1.2 (io), 28 AIN2.1/A9/P1.1 (io), 29 AIN2.0/A8/P1.0 (io), 30 A15m/A7/P2.7 (io), 31 A14m/A6/P2.6 (io), 32 A13m/A5/P2.5 (io), 33 A12m/A4/P2.4 (io), 34 A11m/A3/P2.3 (io), 35 A10m/A2/P2.2 (io), 36 A9m/A1/P2.1 (io), 37 A8m/A0/P2.0 (io), 38 AD7/D7/P3.7 (io), 39 AD6/D6/P3.6 (io), 42 AD5/D5/P3.5 (io), 43 AD4/D4/P3.4 (io), 44 AD3/D3/P3.3 (io), 45 AD2/D2/P3.2 (io), 46 AD1/D1/P3.1 (io), 47 AD0/D0/P3.0 (io), 48 ~{WR}/P0.7 (io), 49 ~{RD}/P0.6 (io), 50 ALE/P0.5 (io), 51 P0.4 (io), 52 P0.3 (io), 53 P0.2 (io), 54 P0.1 (io), 55 P0.0 (io)
part B pins: 1 CP1- (in), 2 CP1+ (in), 3 CP0- (in), 4 CP0+ (in), 7 VREF (io), 8 VREF0 (in), 9 AIN0.0 (in), 10 AIN0.1 (in), 11 AIN0.2 (in), 12 AIN0.3 (in), 13 AIN0.4 (in), 14 AIN0.5 (in), 15 AIN0.6 (in), 16 AIN0.7 (in), 17 XTAL1 (in), 18 XTAL2 (out), 19 MONEN (in), 62 ~{RST} (io), 63 NC, 64 NC
part C pins: 58 TMS (in), 59 TCK (in), 60 TDI (in), 61 TDO (hiz)
part D pins: 5 AGND (power), 6 AV+ (power), 24 VDD (power), 25 DGND (power), 40 DGND (power), 41 VDD (power), 56 DGND (power), 57 VDD (power)

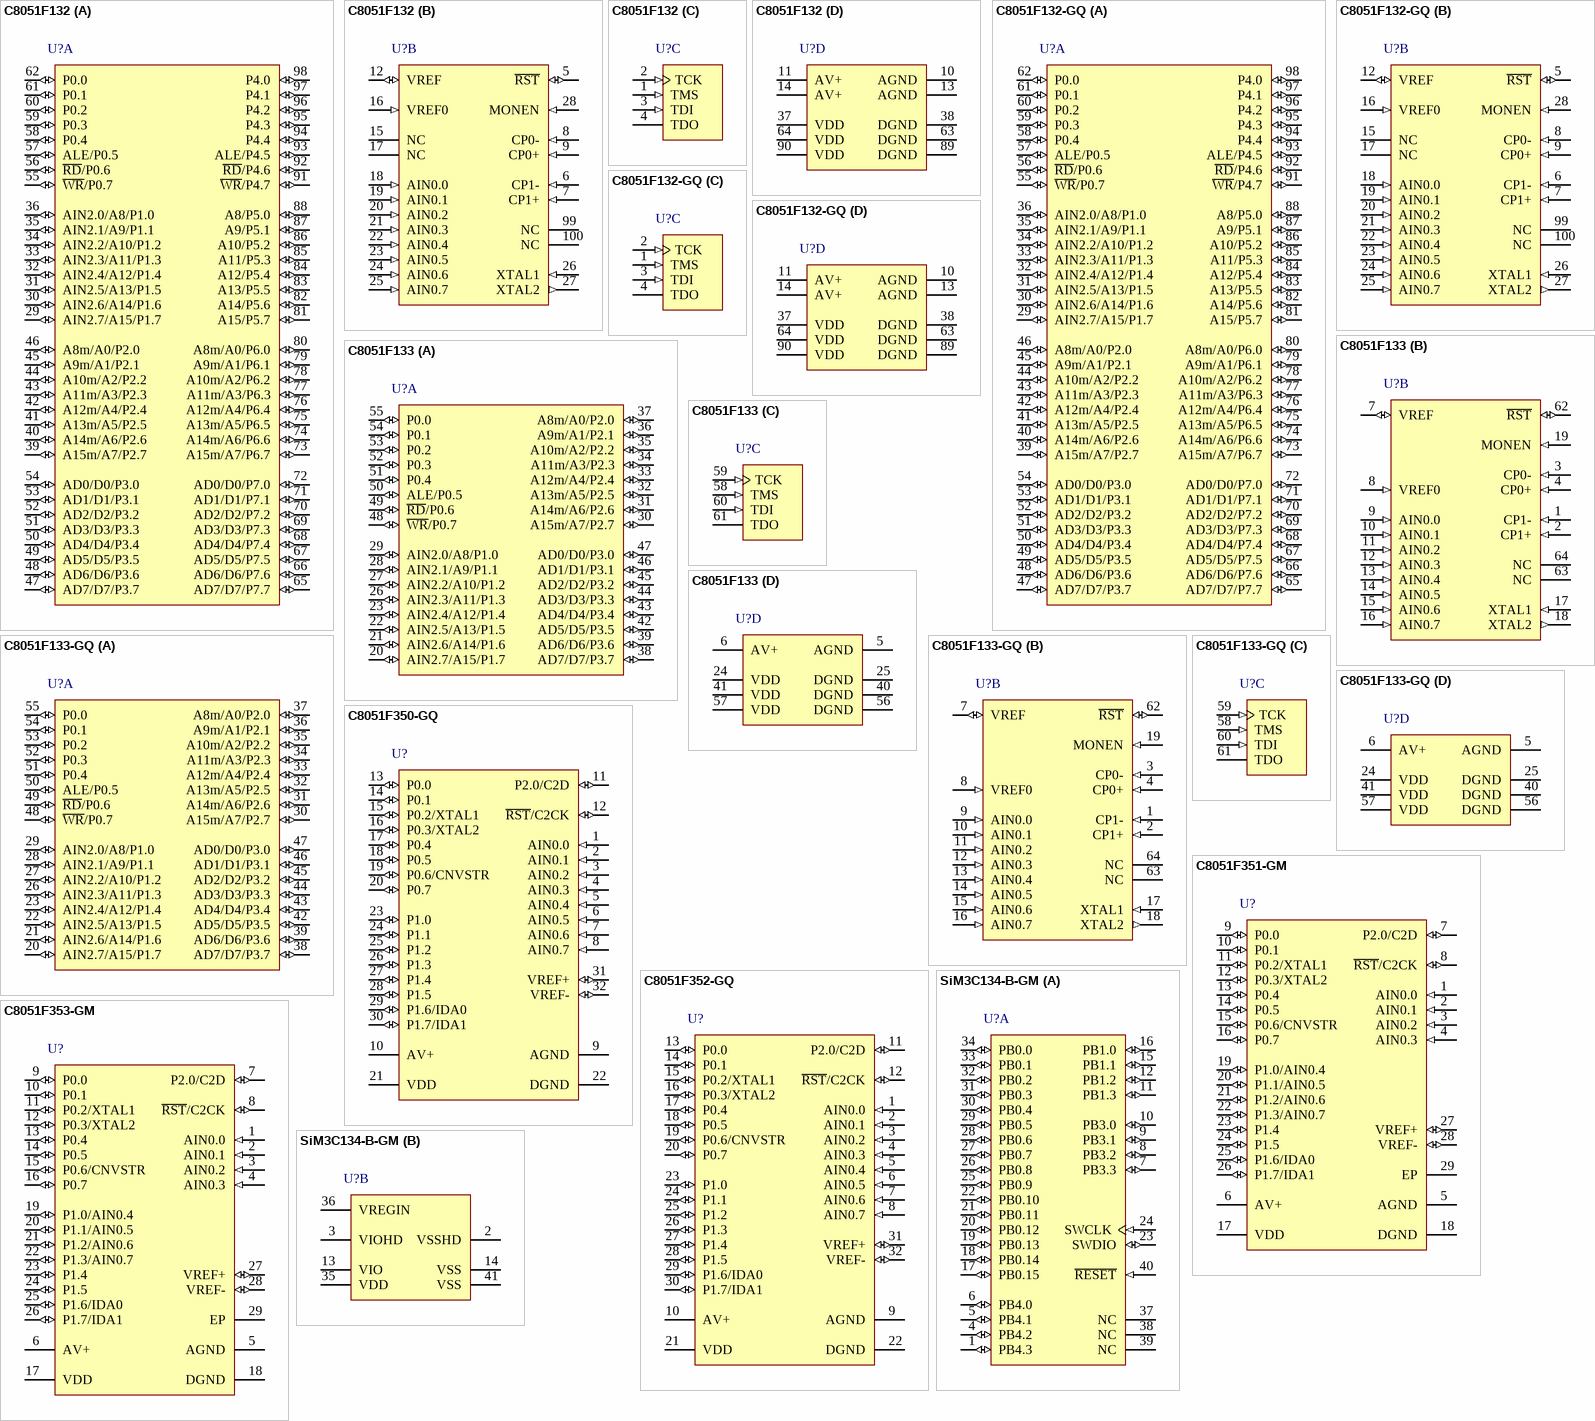
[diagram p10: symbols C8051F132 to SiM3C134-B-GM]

## C8051F132
designator U?
Mixed Signal 64KB ISP Flash MCU, 100 MIPS, 8448B RAM, 64 I/Os, 10-Bit ADC, 100-Pin TQFP; Manufacturer: Silicon Labs; PartNumber: C8051F132
footprint TQFP-100_N (Thin QFP, 100-Leads, Body 14x14mm, Pitch 0.5mm, IPC Medium Density)
footprint TQFP-100_L (Thin QFP, 100-Leads, Body 14x14mm, Pitch 0.5mm, IPC High Density)
footprint TQFP-100_M (Thin QFP, 100-Leads, Body 14x14mm, Pitch 0.5mm, IPC Low Density)
part A pins: 29 AIN2.7/A15/P1.7 (io), 30 AIN2.6/A14/P1.6 (io), 31 AIN2.5/A13/P1.5 (io), 32 AIN2.4/A12/P1.4 (io), 33 AIN2.3/A11/P1.3 (io), 34 AIN2.2/A10/P1.2 (io), 35 AIN2.1/A9/P1.1 (io), 36 AIN2.0/A8/P1.0 (io), 39 A15m/A7/P2.7 (io), 40 A14m/A6/P2.6 (io), 41 A13m/A5/P2.5 (io), 42 A12m/A4/P2.4 (io), 43 A11m/A3/P2.3 (io), 44 A10m/A2/P2.2 (io), 45 A9m/A1/P2.1 (io), 46 A8m/A0/P2.0 (io), 47 AD7/D7/P3.7 (io), 48 AD6/D6/P3.6 (io), 49 AD5/D5/P3.5 (io), 50 AD4/D4/P3.4 (io), 51 AD3/D3/P3.3 (io), 52 AD2/D2/P3.2 (io), 53 AD1/D1/P3.1 (io), 54 AD0/D0/P3.0 (io), 55 ~{WR}/P0.7 (io), 56 ~{RD}/P0.6 (io), 57 ALE/P0.5 (io), 58 P0.4 (io), 59 P0.3 (io), 60 P0.2 (io), 61 P0.1 (io), 62 P0.0 (io), 65 AD7/D7/P7.7 (io), 66 AD6/D6/P7.6 (io), 67 AD5/D5/P7.5 (io), 68 AD4/D4/P7.4 (io), 69 AD3/D3/P7.3 (io), 70 AD2/D2/P7.2 (io), 71 AD1/D1/P7.1 (io), 72 AD0/D0/P7.0 (io), 73 A15m/A7/P6.7 (io), 74 A14m/A6/P6.6 (io), 75 A13m/A5/P6.5 (io), 76 A12m/A4/P6.4 (io), 77 A11m/A3/P6.3 (io), 78 A10m/A2/P6.2 (io), 79 A9m/A1/P6.1 (io), 80 A8m/A0/P6.0 (io), 81 A15/P5.7 (io), 82 A14/P5.6 (io), 83 A13/P5.5 (io), 84 A12/P5.4 (io), 85 A11/P5.3 (io), 86 A10/P5.2 (io), 87 A9/P5.1 (io), 88 A8/P5.0 (io), 91 ~{WR}/P4.7 (io), 92 ~{RD}/P4.6 (io), 93 ALE/P4.5 (io), 94 P4.4 (io), 95 P4.3 (io), 96 P4.2 (io), 97 P4.1 (io), 98 P4.0 (io)
part B pins: 5 ~{RST} (io), 6 CP1- (in), 7 CP1+ (in), 8 CP0- (in), 9 CP0+ (in), 12 VREF (io), 15 NC, 16 VREF0 (in), 17 NC, 18 AIN0.0 (in), 19 AIN0.1 (in), 20 AIN0.2 (in), 21 AIN0.3 (in), 22 AIN0.4 (in), 23 AIN0.5 (in), 24 AIN0.6 (in), 25 AIN0.7 (in), 26 XTAL1 (in), 27 XTAL2 (out), 28 MONEN (in), 99 NC, 100 NC
part C pins: 1 TMS (in), 2 TCK (in), 3 TDI (in), 4 TDO (hiz)
part D pins: 10 AGND (power), 11 AV+ (power), 13 AGND (power), 14 AV+ (power), 37 VDD (power), 38 DGND (power), 63 DGND (power), 64 VDD (power), 89 DGND (power), 90 VDD (power)

## C8051F132-GQ
designator U?
Mixed Signal 64KB ISP Flash MCU, 100 MIPS, 8448B RAM, 64 I/Os, 10-Bit ADC, 100-Pin TQFP, Pb-Free; Manufacturer: Silicon Labs; PartNumber: C8051F132-GQ
footprint TQFP-100_N (Thin QFP, 100-Leads, Body 14x14mm, Pitch 0.5mm, IPC Medium Density)
footprint TQFP-100_L (Thin QFP, 100-Leads, Body 14x14mm, Pitch 0.5mm, IPC High Density)
footprint TQFP-100_M (Thin QFP, 100-Leads, Body 14x14mm, Pitch 0.5mm, IPC Low Density)
part A pins: 29 AIN2.7/A15/P1.7 (io), 30 AIN2.6/A14/P1.6 (io), 31 AIN2.5/A13/P1.5 (io), 32 AIN2.4/A12/P1.4 (io), 33 AIN2.3/A11/P1.3 (io), 34 AIN2.2/A10/P1.2 (io), 35 AIN2.1/A9/P1.1 (io), 36 AIN2.0/A8/P1.0 (io), 39 A15m/A7/P2.7 (io), 40 A14m/A6/P2.6 (io), 41 A13m/A5/P2.5 (io), 42 A12m/A4/P2.4 (io), 43 A11m/A3/P2.3 (io), 44 A10m/A2/P2.2 (io), 45 A9m/A1/P2.1 (io), 46 A8m/A0/P2.0 (io), 47 AD7/D7/P3.7 (io), 48 AD6/D6/P3.6 (io), 49 AD5/D5/P3.5 (io), 50 AD4/D4/P3.4 (io), 51 AD3/D3/P3.3 (io), 52 AD2/D2/P3.2 (io), 53 AD1/D1/P3.1 (io), 54 AD0/D0/P3.0 (io), 55 ~{WR}/P0.7 (io), 56 ~{RD}/P0.6 (io), 57 ALE/P0.5 (io), 58 P0.4 (io), 59 P0.3 (io), 60 P0.2 (io), 61 P0.1 (io), 62 P0.0 (io), 65 AD7/D7/P7.7 (io), 66 AD6/D6/P7.6 (io), 67 AD5/D5/P7.5 (io), 68 AD4/D4/P7.4 (io), 69 AD3/D3/P7.3 (io), 70 AD2/D2/P7.2 (io), 71 AD1/D1/P7.1 (io), 72 AD0/D0/P7.0 (io), 73 A15m/A7/P6.7 (io), 74 A14m/A6/P6.6 (io), 75 A13m/A5/P6.5 (io), 76 A12m/A4/P6.4 (io), 77 A11m/A3/P6.3 (io), 78 A10m/A2/P6.2 (io), 79 A9m/A1/P6.1 (io), 80 A8m/A0/P6.0 (io), 81 A15/P5.7 (io), 82 A14/P5.6 (io), 83 A13/P5.5 (io), 84 A12/P5.4 (io), 85 A11/P5.3 (io), 86 A10/P5.2 (io), 87 A9/P5.1 (io), 88 A8/P5.0 (io), 91 ~{WR}/P4.7 (io), 92 ~{RD}/P4.6 (io), 93 ALE/P4.5 (io), 94 P4.4 (io), 95 P4.3 (io), 96 P4.2 (io), 97 P4.1 (io), 98 P4.0 (io)
part B pins: 5 ~{RST} (io), 6 CP1- (in), 7 CP1+ (in), 8 CP0- (in), 9 CP0+ (in), 12 VREF (io), 15 NC, 16 VREF0 (in), 17 NC, 18 AIN0.0 (in), 19 AIN0.1 (in), 20 AIN0.2 (in), 21 AIN0.3 (in), 22 AIN0.4 (in), 23 AIN0.5 (in), 24 AIN0.6 (in), 25 AIN0.7 (in), 26 XTAL1 (in), 27 XTAL2 (out), 28 MONEN (in), 99 NC, 100 NC
part C pins: 1 TMS (in), 2 TCK (in), 3 TDI (in), 4 TDO (hiz)
part D pins: 10 AGND (power), 11 AV+ (power), 13 AGND (power), 14 AV+ (power), 37 VDD (power), 38 DGND (power), 63 DGND (power), 64 VDD (power), 89 DGND (power), 90 VDD (power)

## C8051F133
designator U?
Mixed Signal 64KB ISP Flash MCU, 100 MIPS, 8448B RAM, 32 I/Os, 10-Bit ADC, 64-Pin TQFP; Manufacturer: Silicon Labs; PartNumber: C8051F133
footprint TQFP-64_N (Thin QFP, 64-Leads, Body 10x10mm, Pitch 0.5mm, IPC Medium Density)
footprint TQFP-64_L (Thin QFP, 64-Leads, Body 10x10mm, Pitch 0.5mm, IPC High Density)
footprint TQFP-64_M (Thin QFP, 64-Leads, Body 10x10mm, Pitch 0.5mm, IPC Low Density)
part A pins: 20 AIN2.7/A15/P1.7 (io), 21 AIN2.6/A14/P1.6 (io), 22 AIN2.5/A13/P1.5 (io), 23 AIN2.4/A12/P1.4 (io), 26 AIN2.3/A11/P1.3 (io), 27 AIN2.2/A10/P1.2 (io), 28 AIN2.1/A9/P1.1 (io), 29 AIN2.0/A8/P1.0 (io), 30 A15m/A7/P2.7 (io), 31 A14m/A6/P2.6 (io), 32 A13m/A5/P2.5 (io), 33 A12m/A4/P2.4 (io), 34 A11m/A3/P2.3 (io), 35 A10m/A2/P2.2 (io), 36 A9m/A1/P2.1 (io), 37 A8m/A0/P2.0 (io), 38 AD7/D7/P3.7 (io), 39 AD6/D6/P3.6 (io), 42 AD5/D5/P3.5 (io), 43 AD4/D4/P3.4 (io), 44 AD3/D3/P3.3 (io), 45 AD2/D2/P3.2 (io), 46 AD1/D1/P3.1 (io), 47 AD0/D0/P3.0 (io), 48 ~{WR}/P0.7 (io), 49 ~{RD}/P0.6 (io), 50 ALE/P0.5 (io), 51 P0.4 (io), 52 P0.3 (io), 53 P0.2 (io), 54 P0.1 (io), 55 P0.0 (io)
part B pins: 1 CP1- (in), 2 CP1+ (in), 3 CP0- (in), 4 CP0+ (in), 7 VREF (io), 8 VREF0 (in), 9 AIN0.0 (in), 10 AIN0.1 (in), 11 AIN0.2 (in), 12 AIN0.3 (in), 13 AIN0.4 (in), 14 AIN0.5 (in), 15 AIN0.6 (in), 16 AIN0.7 (in), 17 XTAL1 (in), 18 XTAL2 (out), 19 MONEN (in), 62 ~{RST} (io), 63 NC, 64 NC
part C pins: 58 TMS (in), 59 TCK (in), 60 TDI (in), 61 TDO (hiz)
part D pins: 5 AGND (power), 6 AV+ (power), 24 VDD (power), 25 DGND (power), 40 DGND (power), 41 VDD (power), 56 DGND (power), 57 VDD (power)

## C8051F133-GQ
designator U?
Mixed Signal 64KB ISP Flash MCU, 100 MIPS, 8448B RAM, 32 I/Os, 10-Bit ADC, 64-Pin TQFP, Pb-Free; Manufacturer: Silicon Labs; PartNumber: C8051F133-GQ
footprint TQFP-64_N (Thin QFP, 64-Leads, Body 10x10mm, Pitch 0.5mm, IPC Medium Density)
footprint TQFP-64_L (Thin QFP, 64-Leads, Body 10x10mm, Pitch 0.5mm, IPC High Density)
footprint TQFP-64_M (Thin QFP, 64-Leads, Body 10x10mm, Pitch 0.5mm, IPC Low Density)
part A pins: 20 AIN2.7/A15/P1.7 (io), 21 AIN2.6/A14/P1.6 (io), 22 AIN2.5/A13/P1.5 (io), 23 AIN2.4/A12/P1.4 (io), 26 AIN2.3/A11/P1.3 (io), 27 AIN2.2/A10/P1.2 (io), 28 AIN2.1/A9/P1.1 (io), 29 AIN2.0/A8/P1.0 (io), 30 A15m/A7/P2.7 (io), 31 A14m/A6/P2.6 (io), 32 A13m/A5/P2.5 (io), 33 A12m/A4/P2.4 (io), 34 A11m/A3/P2.3 (io), 35 A10m/A2/P2.2 (io), 36 A9m/A1/P2.1 (io), 37 A8m/A0/P2.0 (io), 38 AD7/D7/P3.7 (io), 39 AD6/D6/P3.6 (io), 42 AD5/D5/P3.5 (io), 43 AD4/D4/P3.4 (io), 44 AD3/D3/P3.3 (io), 45 AD2/D2/P3.2 (io), 46 AD1/D1/P3.1 (io), 47 AD0/D0/P3.0 (io), 48 ~{WR}/P0.7 (io), 49 ~{RD}/P0.6 (io), 50 ALE/P0.5 (io), 51 P0.4 (io), 52 P0.3 (io), 53 P0.2 (io), 54 P0.1 (io), 55 P0.0 (io)
part B pins: 1 CP1- (in), 2 CP1+ (in), 3 CP0- (in), 4 CP0+ (in), 7 VREF (io), 8 VREF0 (in), 9 AIN0.0 (in), 10 AIN0.1 (in), 11 AIN0.2 (in), 12 AIN0.3 (in), 13 AIN0.4 (in), 14 AIN0.5 (in), 15 AIN0.6 (in), 16 AIN0.7 (in), 17 XTAL1 (in), 18 XTAL2 (out), 19 MONEN (in), 62 ~{RST} (io), 63 NC, 64 NC
part C pins: 58 TMS (in), 59 TCK (in), 60 TDI (in), 61 TDO (hiz)
part D pins: 5 AGND (power), 6 AV+ (power), 24 VDD (power), 25 DGND (power), 40 DGND (power), 41 VDD (power), 56 DGND (power), 57 VDD (power)

## C8051F350-GQ
designator U?
8KB ISP Flash MCU, 50 MIPS, 768B RAM, 17 I/Os, UART, I2C, SPI, 24-Bit DAC, 32-Pin LQFP, Pb-Free; Manufacturer: Silicon Labs; PartNumber: C8051F350-GQ
footprint LQFP-32_N (Thin QFP, 32-Leads, Body 7x7mm, Pitch 0.8mm, IPC Medium Density)
footprint LQFP-32_L (Thin QFP, 32-Leads, Body 7x7mm, Pitch 0.8mm, IPC High Density)
footprint LQFP-32_M (Thin QFP, 32-Leads, Body 7x7mm, Pitch 0.8mm, IPC Low Density)
pins: 1 AIN0.0 (in), 2 AIN0.1 (in), 3 AIN0.2 (in), 4 AIN0.3 (in), 5 AIN0.4 (in), 6 AIN0.5 (in), 7 AIN0.6 (in), 8 AIN0.7 (in), 9 AGND (power), 10 AV+ (power), 11 P2.0/C2D (io), 12 ~{RST}/C2CK (io), 13 P0.0 (io), 14 P0.1 (io), 15 P0.2/XTAL1 (io), 16 P0.3/XTAL2 (io), 17 P0.4 (io), 18 P0.5 (io), 19 P0.6/CNVSTR (io), 20 P0.7 (io), 21 VDD (power), 22 DGND (power), 23 P1.0 (io), 24 P1.1 (io), 25 P1.2 (io), 26 P1.3 (io), 27 P1.4 (io), 28 P1.5 (io), 29 P1.6/IDA0 (io), 30 P1.7/IDA1 (io), 31 VREF+ (io), 32 VREF- (io)

## C8051F351-GM
designator U?
8KB ISP Flash MCU, 50 MIPS, 768B RAM, 17 I/Os, UART, I2C, SPI, 24-Bit DAC, 28-Pin QFN, Pb-Free; Manufacturer: Silicon Labs; PartNumber: C8051F351-GM
footprint QFN-28_V (QFN, 28-Leads, Body 5x5mm, Pitch 0.5mm, Thermal Pad 3.15x3.15mm, Silicon Labs Recommended)
pins: 1 AIN0.0 (in), 2 AIN0.1 (in), 3 AIN0.2 (in), 4 AIN0.3 (in), 5 AGND (power), 6 AV+ (power), 7 P2.0/C2D (io), 8 ~{RST}/C2CK (io), 9 P0.0 (io), 10 P0.1 (io), 11 P0.2/XTAL1 (io), 12 P0.3/XTAL2 (io), 13 P0.4 (io), 14 P0.5 (io), 15 P0.6/CNVSTR (io), 16 P0.7 (io), 17 VDD (power), 18 DGND (power), 19 P1.0/AIN0.4 (io), 20 P1.1/AIN0.5 (io), 21 P1.2/AIN0.6 (io), 22 P1.3/AIN0.7 (io), 23 P1.4 (io), 24 P1.5 (io), 25 P1.6/IDA0 (io), 26 P1.7/IDA1 (io), 27 VREF+ (io), 28 VREF- (io), 29 EP (power)

## C8051F352-GQ
designator U?
8KB ISP Flash MCU, 50 MIPS, 768B RAM, 17 I/Os, UART, I2C, SPI, 16-Bit DAC, 32-Pin LQFP, Pb-Free; Manufacturer: Silicon Labs; PartNumber: C8051F352-GQ
footprint LQFP-32_N (Thin QFP, 32-Leads, Body 7x7mm, Pitch 0.8mm, IPC Medium Density)
footprint LQFP-32_L (Thin QFP, 32-Leads, Body 7x7mm, Pitch 0.8mm, IPC High Density)
footprint LQFP-32_M (Thin QFP, 32-Leads, Body 7x7mm, Pitch 0.8mm, IPC Low Density)
pins: 1 AIN0.0 (in), 2 AIN0.1 (in), 3 AIN0.2 (in), 4 AIN0.3 (in), 5 AIN0.4 (in), 6 AIN0.5 (in), 7 AIN0.6 (in), 8 AIN0.7 (in), 9 AGND (power), 10 AV+ (power), 11 P2.0/C2D (io), 12 ~{RST}/C2CK (io), 13 P0.0 (io), 14 P0.1 (io), 15 P0.2/XTAL1 (io), 16 P0.3/XTAL2 (io), 17 P0.4 (io), 18 P0.5 (io), 19 P0.6/CNVSTR (io), 20 P0.7 (io), 21 VDD (power), 22 DGND (power), 23 P1.0 (io), 24 P1.1 (io), 25 P1.2 (io), 26 P1.3 (io), 27 P1.4 (io), 28 P1.5 (io), 29 P1.6/IDA0 (io), 30 P1.7/IDA1 (io), 31 VREF+ (io), 32 VREF- (io)

## C8051F353-GM
designator U?
8KB ISP Flash MCU, 50 MIPS, 768B RAM, 17 I/Os, UART, I2C, SPI, 16-Bit DAC, 28-Pin QFN, Pb-Free; Manufacturer: Silicon Labs; PartNumber: C8051F353-GM
footprint QFN-28_V (QFN, 28-Leads, Body 5x5mm, Pitch 0.5mm, Thermal Pad 3.15x3.15mm, Silicon Labs Recommended)
pins: 1 AIN0.0 (in), 2 AIN0.1 (in), 3 AIN0.2 (in), 4 AIN0.3 (in), 5 AGND (power), 6 AV+ (power), 7 P2.0/C2D (io), 8 ~{RST}/C2CK (io), 9 P0.0 (io), 10 P0.1 (io), 11 P0.2/XTAL1 (io), 12 P0.3/XTAL2 (io), 13 P0.4 (io), 14 P0.5 (io), 15 P0.6/CNVSTR (io), 16 P0.7 (io), 17 VDD (power), 18 DGND (power), 19 P1.0/AIN0.4 (io), 20 P1.1/AIN0.5 (io), 21 P1.2/AIN0.6 (io), 22 P1.3/AIN0.7 (io), 23 P1.4 (io), 24 P1.5 (io), 25 P1.6/IDA0 (io), 26 P1.7/IDA1 (io), 27 VREF+ (io), 28 VREF- (io), 29 EP (power)

## SiM3C134-B-GM
designator U?
High-Performance, Low-Power, 32-Bit Precision32(TM) MCU Family, 80 MHz, 8 kB RAM, 32 kB Flash, -40 to 85 degC, 40-pin QFN; Manufacturer: Silicon Labs; PartNumber: SiM3C134-B-GM; ADC 1: 12-bit, 7-ch., 250 ksps; ADC 2: 12-bit, 11-ch., 250 ksps; AEC-Q100: FALSE; Comparators: 2; DAC: 10-bit, 2-ch.; Debug Interface: SW; Dig I/O Pins: 28; Flash: 32 kB; Internal Osc. Accuracy: +/-1.5%; MCU Core: ARM Cortex-M3; MHz: 80; PCA Channels: 10; RAM: 8 kB; Temp Sensor: TRUE; Timers (16-bit): 4; Sub-Family: Analog Intensive MCUs
footprint SLAB-QFN-40-4500x4500TP_N (QFN, 40-Leads, Body 6x6mm, Pitch 0.5mm, Thermal Pad 4.5x4.5mm, IPC Medium Density)
footprint SLAB-QFN-40-4500x4500TP_L (QFN, 40-Leads, Body 6x6mm, Pitch 0.5mm, Thermal Pad 4.5x4.5mm, IPC High Density)
footprint SLAB-QFN-40-4500x4500TP_M (QFN, 40-Leads, Body 6x6mm, Pitch 0.5mm, Thermal Pad 4.5x4.5mm, IPC Low Density)
part A pins: 1 PB4.3 (io), 4 PB4.2 (io), 5 PB4.1 (io), 6 PB4.0 (io), 7 PB3.3 (io), 8 PB3.2 (io), 9 PB3.1 (io), 10 PB3.0 (io), 11 PB1.3 (io), 12 PB1.2 (io), 15 PB1.1 (io), 16 PB1.0 (io), 17 PB0.15 (io), 18 PB0.14 (io), 19 PB0.13 (io), 20 PB0.12 (io), 21 PB0.11 (io), 22 PB0.10 (io), 23 SWDIO (io), 24 SWCLK (in), 25 PB0.9 (io), 26 PB0.8 (io), 27 PB0.7 (io), 28 PB0.6 (io), 29 PB0.5 (io), 30 PB0.4 (io), 31 PB0.3 (io), 32 PB0.2 (io), 33 PB0.1 (io), 34 PB0.0 (io), 37 NC, 38 NC, 39 NC, 40 ~{RESET} (in)
part B pins: 2 VSSHD (power), 3 VIOHD (power), 13 VIO (power), 14 VSS (power), 35 VDD (power), 36 VREGIN (power), 41 VSS (power)

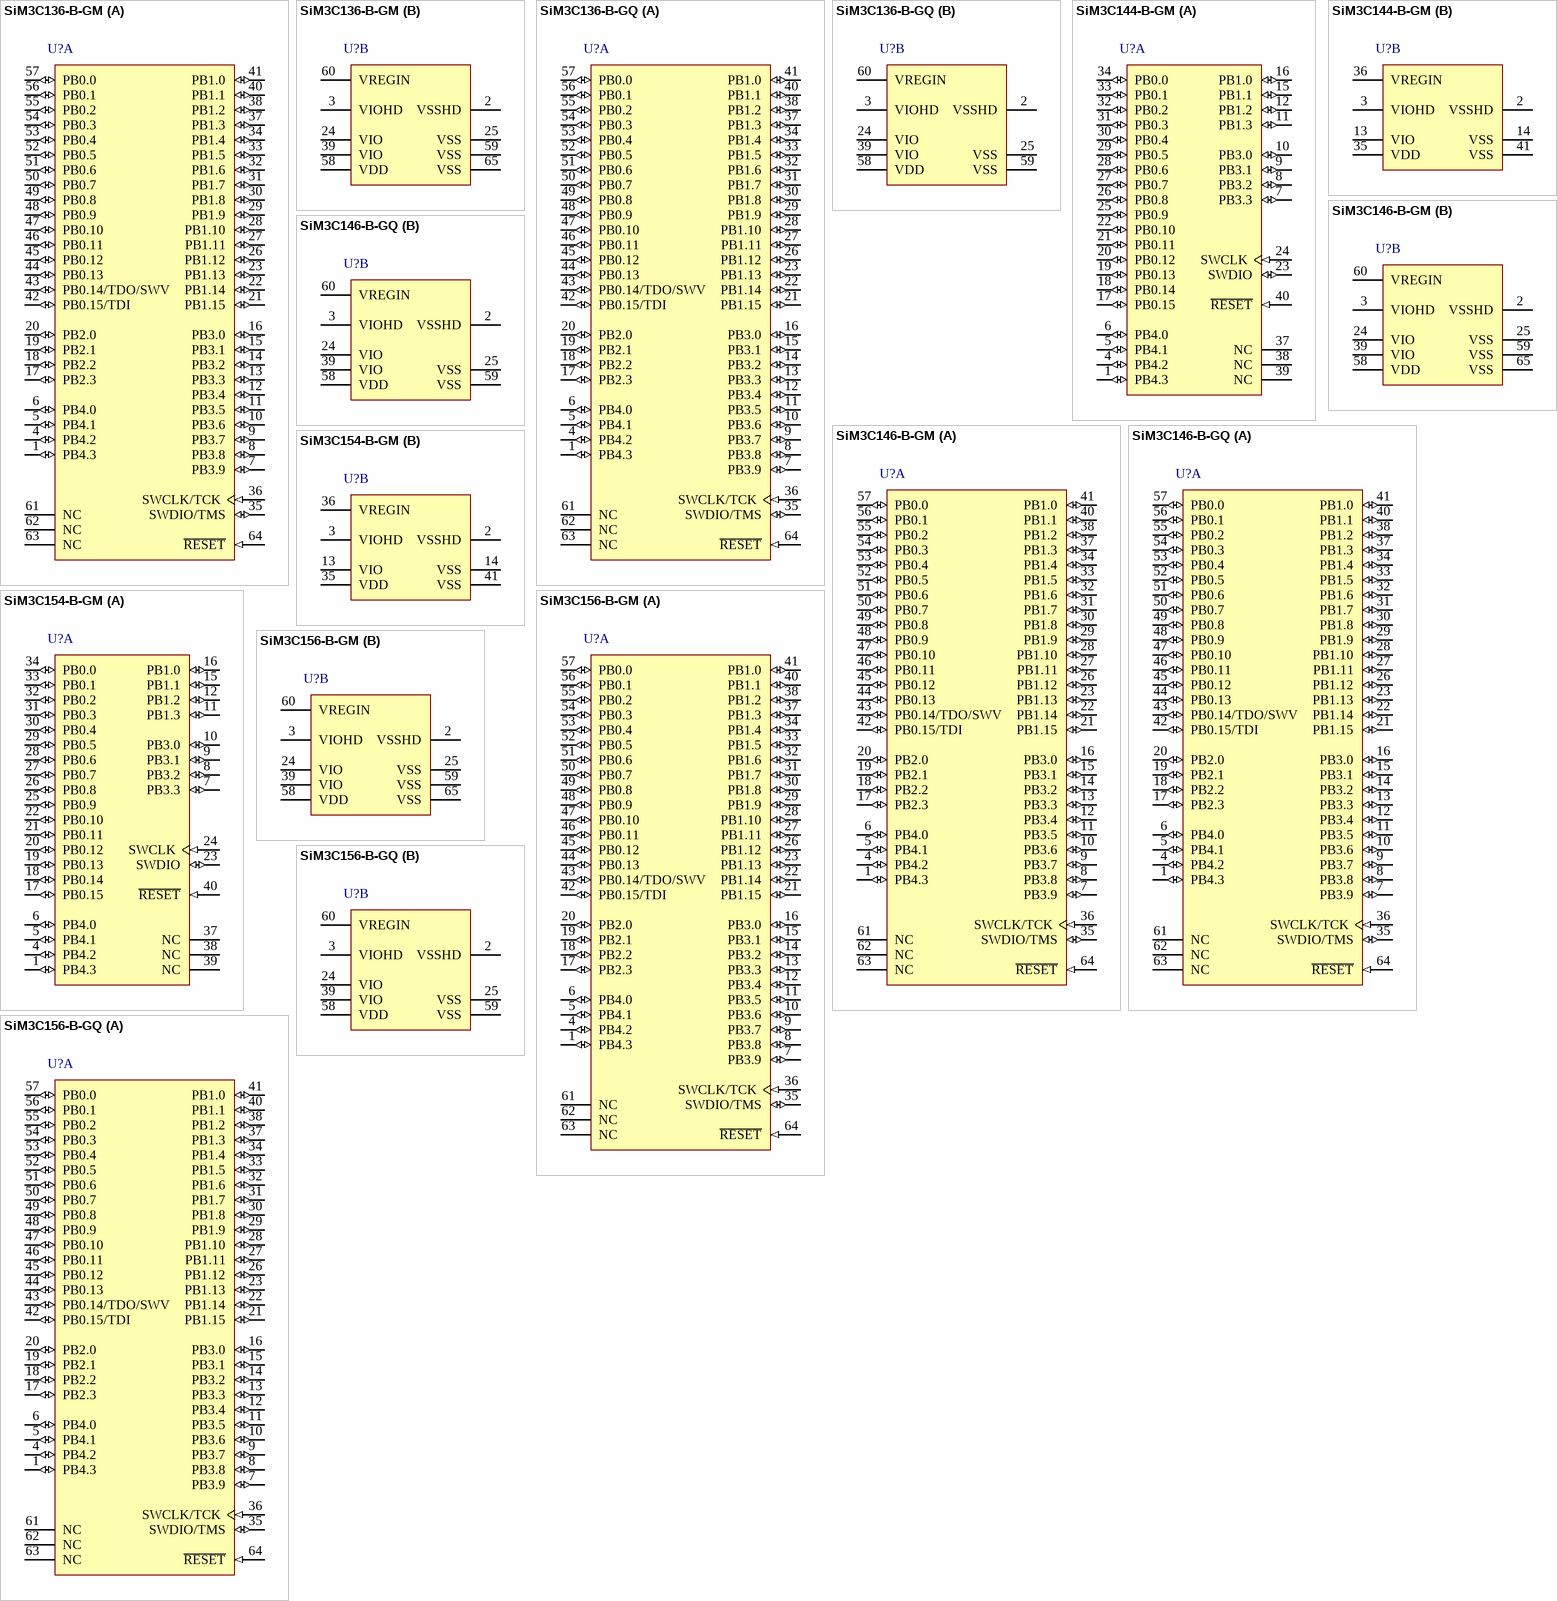
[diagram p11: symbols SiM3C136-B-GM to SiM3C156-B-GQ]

## SiM3C136-B-GM
designator U?
High-Performance, Low-Power, 32-Bit Precision32(TM) MCU Family, 80 MHz, 8 kB RAM, 32 kB Flash, -40 to 85 degC, 64-pin QFN; Manufacturer: Silicon Labs; PartNumber: SiM3C136-B-GM; ADC 1: 12-bit, 13-ch., 250 ksps; ADC 2: 12-bit, 15-ch., 250 ksps; AEC-Q100: FALSE; Comparators: 2; DAC: 10-bit, 2-ch.; Debug Interface: JTAG; SW; Dig I/O Pins: 50; Flash: 32 kB; Internal Osc. Accuracy: +/-1.5%; MCU Core: ARM Cortex-M3; MHz: 80; PCA Channels: 10; RAM: 8 kB; Temp Sensor: TRUE; Timers (16-bit): 4; Sub-Family: Analog Intensive MCUs
footprint SLAB-QFN-64-4100x4100TP_N (QFN, 64-Leads, Body 9x9mm, Pitch 0.5mm, Thermal Pad 4.1x4.1mm, IPC Medium Density)
footprint SLAB-QFN-64-4100x4100TP_L (QFN, 64-Leads, Body 9x9mm, Pitch 0.5mm, Thermal Pad 4.1x4.1mm, IPC High Density)
footprint SLAB-QFN-64-4100x4100TP_M (QFN, 64-Leads, Body 9x9mm, Pitch 0.5mm, Thermal Pad 4.1x4.1mm, IPC Low Density)
part A pins: 1 PB4.3 (io), 4 PB4.2 (io), 5 PB4.1 (io), 6 PB4.0 (io), 7 PB3.9 (io), 8 PB3.8 (io), 9 PB3.7 (io), 10 PB3.6 (io), 11 PB3.5 (io), 12 PB3.4 (io), 13 PB3.3 (io), 14 PB3.2 (io), 15 PB3.1 (io), 16 PB3.0 (io), 17 PB2.3 (io), 18 PB2.2 (io), 19 PB2.1 (io), 20 PB2.0 (io), 21 PB1.15 (io), 22 PB1.14 (io), 23 PB1.13 (io), 26 PB1.12 (io), 27 PB1.11 (io), 28 PB1.10 (io), 29 PB1.9 (io), 30 PB1.8 (io), 31 PB1.7 (io), 32 PB1.6 (io), 33 PB1.5 (io), 34 PB1.4 (io), 35 SWDIO/TMS (io), 36 SWCLK/TCK (in), 37 PB1.3 (io), 38 PB1.2 (io), 40 PB1.1 (io), 41 PB1.0 (io), 42 PB0.15/TDI (io), 43 PB0.14/TDO/SWV (io), 44 PB0.13 (io), 45 PB0.12 (io), 46 PB0.11 (io), 47 PB0.10 (io), 48 PB0.9 (io), 49 PB0.8 (io), 50 PB0.7 (io), 51 PB0.6 (io), 52 PB0.5 (io), 53 PB0.4 (io), 54 PB0.3 (io), 55 PB0.2 (io), 56 PB0.1 (io), 57 PB0.0 (io), 61 NC, 62 NC, 63 NC, 64 ~{RESET} (in)
part B pins: 2 VSSHD (power), 3 VIOHD (power), 24 VIO (power), 25 VSS (power), 39 VIO (power), 58 VDD (power), 59 VSS (power), 60 VREGIN (power), 65 VSS (power)

## SiM3C136-B-GQ
designator U?
High-Performance, Low-Power, 32-Bit Precision32(TM) MCU Family, 80 MHz, 8 kB RAM, 32 kB Flash, -40 to 85 degC, 64-pin QFP; Manufacturer: Silicon Labs; PartNumber: SiM3C136-B-GQ; ADC 1: 12-bit, 13-ch., 250 ksps; ADC 2: 12-bit, 15-ch., 250 ksps; AEC-Q100: FALSE; Comparators: 2; DAC: 10-bit, 2-ch.; Debug Interface: JTAG; SW; Dig I/O Pins: 50; Flash: 32 kB; Internal Osc. Accuracy: +/-1.5%; MCU Core: ARM Cortex-M3; MHz: 80; PCA Channels: 10; RAM: 8 kB; Temp Sensor: TRUE; Timers (16-bit): 4; Sub-Family: Analog Intensive MCUs
footprint SLAB-TQFP-64_N (QFP, 64-Leads, Body 10x10mm, Pitch 0.5mm, IPC Medium Density)
footprint SLAB-TQFP-64_L (QFP, 64-Leads, Body 10x10mm, Pitch 0.5mm, IPC High Density)
footprint SLAB-TQFP-64_M (QFP, 64-Leads, Body 10x10mm, Pitch 0.5mm, IPC Low Density)
part A pins: 1 PB4.3 (io), 4 PB4.2 (io), 5 PB4.1 (io), 6 PB4.0 (io), 7 PB3.9 (io), 8 PB3.8 (io), 9 PB3.7 (io), 10 PB3.6 (io), 11 PB3.5 (io), 12 PB3.4 (io), 13 PB3.3 (io), 14 PB3.2 (io), 15 PB3.1 (io), 16 PB3.0 (io), 17 PB2.3 (io), 18 PB2.2 (io), 19 PB2.1 (io), 20 PB2.0 (io), 21 PB1.15 (io), 22 PB1.14 (io), 23 PB1.13 (io), 26 PB1.12 (io), 27 PB1.11 (io), 28 PB1.10 (io), 29 PB1.9 (io), 30 PB1.8 (io), 31 PB1.7 (io), 32 PB1.6 (io), 33 PB1.5 (io), 34 PB1.4 (io), 35 SWDIO/TMS (io), 36 SWCLK/TCK (in), 37 PB1.3 (io), 38 PB1.2 (io), 40 PB1.1 (io), 41 PB1.0 (io), 42 PB0.15/TDI (io), 43 PB0.14/TDO/SWV (io), 44 PB0.13 (io), 45 PB0.12 (io), 46 PB0.11 (io), 47 PB0.10 (io), 48 PB0.9 (io), 49 PB0.8 (io), 50 PB0.7 (io), 51 PB0.6 (io), 52 PB0.5 (io), 53 PB0.4 (io), 54 PB0.3 (io), 55 PB0.2 (io), 56 PB0.1 (io), 57 PB0.0 (io), 61 NC, 62 NC, 63 NC, 64 ~{RESET} (in)
part B pins: 2 VSSHD (power), 3 VIOHD (power), 24 VIO (power), 25 VSS (power), 39 VIO (power), 58 VDD (power), 59 VSS (power), 60 VREGIN (power)

## SiM3C144-B-GM
designator U?
High-Performance, Low-Power, 32-Bit Precision32(TM) MCU Family, 80 MHz, 16 kB RAM, 64 kB Flash, -40 to 85 degC, 40-pin QFN; Manufacturer: Silicon Labs; PartNumber: SiM3C144-B-GM; ADC 1: 12-bit, 7-ch., 250 ksps; ADC 2: 12-bit, 11-ch., 250 ksps; AEC-Q100: FALSE; Comparators: 2; DAC: 10-bit, 2-ch.; Debug Interface: SW; Dig I/O Pins: 28; Flash: 64 kB; Internal Osc. Accuracy: +/-1.5%; MCU Core: ARM Cortex-M3; MHz: 80; PCA Channels: 10; RAM: 16 kB; Temp Sensor: TRUE; Timers (16-bit): 4; Sub-Family: Analog Intensive MCUs
footprint SLAB-QFN-40-4500x4500TP_N (QFN, 40-Leads, Body 6x6mm, Pitch 0.5mm, Thermal Pad 4.5x4.5mm, IPC Medium Density)
footprint SLAB-QFN-40-4500x4500TP_L (QFN, 40-Leads, Body 6x6mm, Pitch 0.5mm, Thermal Pad 4.5x4.5mm, IPC High Density)
footprint SLAB-QFN-40-4500x4500TP_M (QFN, 40-Leads, Body 6x6mm, Pitch 0.5mm, Thermal Pad 4.5x4.5mm, IPC Low Density)
part A pins: 1 PB4.3 (io), 4 PB4.2 (io), 5 PB4.1 (io), 6 PB4.0 (io), 7 PB3.3 (io), 8 PB3.2 (io), 9 PB3.1 (io), 10 PB3.0 (io), 11 PB1.3 (io), 12 PB1.2 (io), 15 PB1.1 (io), 16 PB1.0 (io), 17 PB0.15 (io), 18 PB0.14 (io), 19 PB0.13 (io), 20 PB0.12 (io), 21 PB0.11 (io), 22 PB0.10 (io), 23 SWDIO (io), 24 SWCLK (in), 25 PB0.9 (io), 26 PB0.8 (io), 27 PB0.7 (io), 28 PB0.6 (io), 29 PB0.5 (io), 30 PB0.4 (io), 31 PB0.3 (io), 32 PB0.2 (io), 33 PB0.1 (io), 34 PB0.0 (io), 37 NC, 38 NC, 39 NC, 40 ~{RESET} (in)
part B pins: 2 VSSHD (power), 3 VIOHD (power), 13 VIO (power), 14 VSS (power), 35 VDD (power), 36 VREGIN (power), 41 VSS (power)

## SiM3C146-B-GM
designator U?
High-Performance, Low-Power, 32-Bit Precision32(TM) MCU Family, 80 MHz, 16 kB RAM, 64 kB Flash, -40 to 85 degC, 64-pin QFN; Manufacturer: Silicon Labs; PartNumber: SiM3C146-B-GM; ADC 1: 12-bit, 13-ch., 250 ksps; ADC 2: 12-bit, 15-ch., 250 ksps; AEC-Q100: FALSE; Comparators: 2; DAC: 10-bit, 2-ch.; Debug Interface: JTAG; SW; Dig I/O Pins: 50; Flash: 64 kB; Internal Osc. Accuracy: +/-1.5%; MCU Core: ARM Cortex-M3; MHz: 80; PCA Channels: 10; RAM: 16 kB; Temp Sensor: TRUE; Timers (16-bit): 4; Sub-Family: Analog Intensive MCUs
footprint SLAB-QFN-64-4100x4100TP_N (QFN, 64-Leads, Body 9x9mm, Pitch 0.5mm, Thermal Pad 4.1x4.1mm, IPC Medium Density)
footprint SLAB-QFN-64-4100x4100TP_L (QFN, 64-Leads, Body 9x9mm, Pitch 0.5mm, Thermal Pad 4.1x4.1mm, IPC High Density)
footprint SLAB-QFN-64-4100x4100TP_M (QFN, 64-Leads, Body 9x9mm, Pitch 0.5mm, Thermal Pad 4.1x4.1mm, IPC Low Density)
part A pins: 1 PB4.3 (io), 4 PB4.2 (io), 5 PB4.1 (io), 6 PB4.0 (io), 7 PB3.9 (io), 8 PB3.8 (io), 9 PB3.7 (io), 10 PB3.6 (io), 11 PB3.5 (io), 12 PB3.4 (io), 13 PB3.3 (io), 14 PB3.2 (io), 15 PB3.1 (io), 16 PB3.0 (io), 17 PB2.3 (io), 18 PB2.2 (io), 19 PB2.1 (io), 20 PB2.0 (io), 21 PB1.15 (io), 22 PB1.14 (io), 23 PB1.13 (io), 26 PB1.12 (io), 27 PB1.11 (io), 28 PB1.10 (io), 29 PB1.9 (io), 30 PB1.8 (io), 31 PB1.7 (io), 32 PB1.6 (io), 33 PB1.5 (io), 34 PB1.4 (io), 35 SWDIO/TMS (io), 36 SWCLK/TCK (in), 37 PB1.3 (io), 38 PB1.2 (io), 40 PB1.1 (io), 41 PB1.0 (io), 42 PB0.15/TDI (io), 43 PB0.14/TDO/SWV (io), 44 PB0.13 (io), 45 PB0.12 (io), 46 PB0.11 (io), 47 PB0.10 (io), 48 PB0.9 (io), 49 PB0.8 (io), 50 PB0.7 (io), 51 PB0.6 (io), 52 PB0.5 (io), 53 PB0.4 (io), 54 PB0.3 (io), 55 PB0.2 (io), 56 PB0.1 (io), 57 PB0.0 (io), 61 NC, 62 NC, 63 NC, 64 ~{RESET} (in)
part B pins: 2 VSSHD (power), 3 VIOHD (power), 24 VIO (power), 25 VSS (power), 39 VIO (power), 58 VDD (power), 59 VSS (power), 60 VREGIN (power), 65 VSS (power)

## SiM3C146-B-GQ
designator U?
High-Performance, Low-Power, 32-Bit Precision32(TM) MCU Family, 80 MHz, 16 kB RAM, 64 kB Flash, -40 to 85 degC, 64-pin QFP; Manufacturer: Silicon Labs; PartNumber: SiM3C146-B-GQ; ADC 1: 12-bit, 13-ch., 250 ksps; ADC 2: 12-bit, 15-ch., 250 ksps; AEC-Q100: FALSE; Comparators: 2; DAC: 10-bit, 2-ch.; Debug Interface: JTAG; SW; Dig I/O Pins: 50; Flash: 64 kB; Internal Osc. Accuracy: +/-1.5%; MCU Core: ARM Cortex-M3; MHz: 80; PCA Channels: 10; RAM: 16 kB; Temp Sensor: TRUE; Timers (16-bit): 4; Sub-Family: Analog Intensive MCUs
footprint SLAB-TQFP-64_N (QFP, 64-Leads, Body 10x10mm, Pitch 0.5mm, IPC Medium Density)
footprint SLAB-TQFP-64_L (QFP, 64-Leads, Body 10x10mm, Pitch 0.5mm, IPC High Density)
footprint SLAB-TQFP-64_M (QFP, 64-Leads, Body 10x10mm, Pitch 0.5mm, IPC Low Density)
part A pins: 1 PB4.3 (io), 4 PB4.2 (io), 5 PB4.1 (io), 6 PB4.0 (io), 7 PB3.9 (io), 8 PB3.8 (io), 9 PB3.7 (io), 10 PB3.6 (io), 11 PB3.5 (io), 12 PB3.4 (io), 13 PB3.3 (io), 14 PB3.2 (io), 15 PB3.1 (io), 16 PB3.0 (io), 17 PB2.3 (io), 18 PB2.2 (io), 19 PB2.1 (io), 20 PB2.0 (io), 21 PB1.15 (io), 22 PB1.14 (io), 23 PB1.13 (io), 26 PB1.12 (io), 27 PB1.11 (io), 28 PB1.10 (io), 29 PB1.9 (io), 30 PB1.8 (io), 31 PB1.7 (io), 32 PB1.6 (io), 33 PB1.5 (io), 34 PB1.4 (io), 35 SWDIO/TMS (io), 36 SWCLK/TCK (in), 37 PB1.3 (io), 38 PB1.2 (io), 40 PB1.1 (io), 41 PB1.0 (io), 42 PB0.15/TDI (io), 43 PB0.14/TDO/SWV (io), 44 PB0.13 (io), 45 PB0.12 (io), 46 PB0.11 (io), 47 PB0.10 (io), 48 PB0.9 (io), 49 PB0.8 (io), 50 PB0.7 (io), 51 PB0.6 (io), 52 PB0.5 (io), 53 PB0.4 (io), 54 PB0.3 (io), 55 PB0.2 (io), 56 PB0.1 (io), 57 PB0.0 (io), 61 NC, 62 NC, 63 NC, 64 ~{RESET} (in)
part B pins: 2 VSSHD (power), 3 VIOHD (power), 24 VIO (power), 25 VSS (power), 39 VIO (power), 58 VDD (power), 59 VSS (power), 60 VREGIN (power)

## SiM3C154-B-GM
designator U?
High-Performance, Low-Power, 32-Bit Precision32(TM) MCU Family, 80 MHz, 32 kB RAM, 128 kB Flash, -40 to 85 degC, 40-pin QFN; Manufacturer: Silicon Labs; PartNumber: SiM3C154-B-GM; ADC 1: 12-bit, 7-ch., 250 ksps; ADC 2: 12-bit, 11-ch., 250 ksps; AEC-Q100: FALSE; Comparators: 2; DAC: 10-bit, 2-ch.; Debug Interface: SW; Dig I/O Pins: 28; Flash: 128 kB; Internal Osc. Accuracy: +/-1.5%; MCU Core: ARM Cortex-M3; MHz: 80; PCA Channels: 10; RAM: 32 kB; Temp Sensor: TRUE; Timers (16-bit): 4; Sub-Family: Analog Intensive MCUs
footprint SLAB-QFN-40-4500x4500TP_N (QFN, 40-Leads, Body 6x6mm, Pitch 0.5mm, Thermal Pad 4.5x4.5mm, IPC Medium Density)
footprint SLAB-QFN-40-4500x4500TP_L (QFN, 40-Leads, Body 6x6mm, Pitch 0.5mm, Thermal Pad 4.5x4.5mm, IPC High Density)
footprint SLAB-QFN-40-4500x4500TP_M (QFN, 40-Leads, Body 6x6mm, Pitch 0.5mm, Thermal Pad 4.5x4.5mm, IPC Low Density)
part A pins: 1 PB4.3 (io), 4 PB4.2 (io), 5 PB4.1 (io), 6 PB4.0 (io), 7 PB3.3 (io), 8 PB3.2 (io), 9 PB3.1 (io), 10 PB3.0 (io), 11 PB1.3 (io), 12 PB1.2 (io), 15 PB1.1 (io), 16 PB1.0 (io), 17 PB0.15 (io), 18 PB0.14 (io), 19 PB0.13 (io), 20 PB0.12 (io), 21 PB0.11 (io), 22 PB0.10 (io), 23 SWDIO (io), 24 SWCLK (in), 25 PB0.9 (io), 26 PB0.8 (io), 27 PB0.7 (io), 28 PB0.6 (io), 29 PB0.5 (io), 30 PB0.4 (io), 31 PB0.3 (io), 32 PB0.2 (io), 33 PB0.1 (io), 34 PB0.0 (io), 37 NC, 38 NC, 39 NC, 40 ~{RESET} (in)
part B pins: 2 VSSHD (power), 3 VIOHD (power), 13 VIO (power), 14 VSS (power), 35 VDD (power), 36 VREGIN (power), 41 VSS (power)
